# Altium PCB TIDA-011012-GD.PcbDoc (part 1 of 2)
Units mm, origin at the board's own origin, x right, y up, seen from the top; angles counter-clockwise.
Board outline 56 x 53 mm, 4 copper layers (Top Layer, Layer 1, Layer 2, Bottom Layer), stack 1.787 mm thick; 152 components, 63 nets, 416 pads, 728 vias.
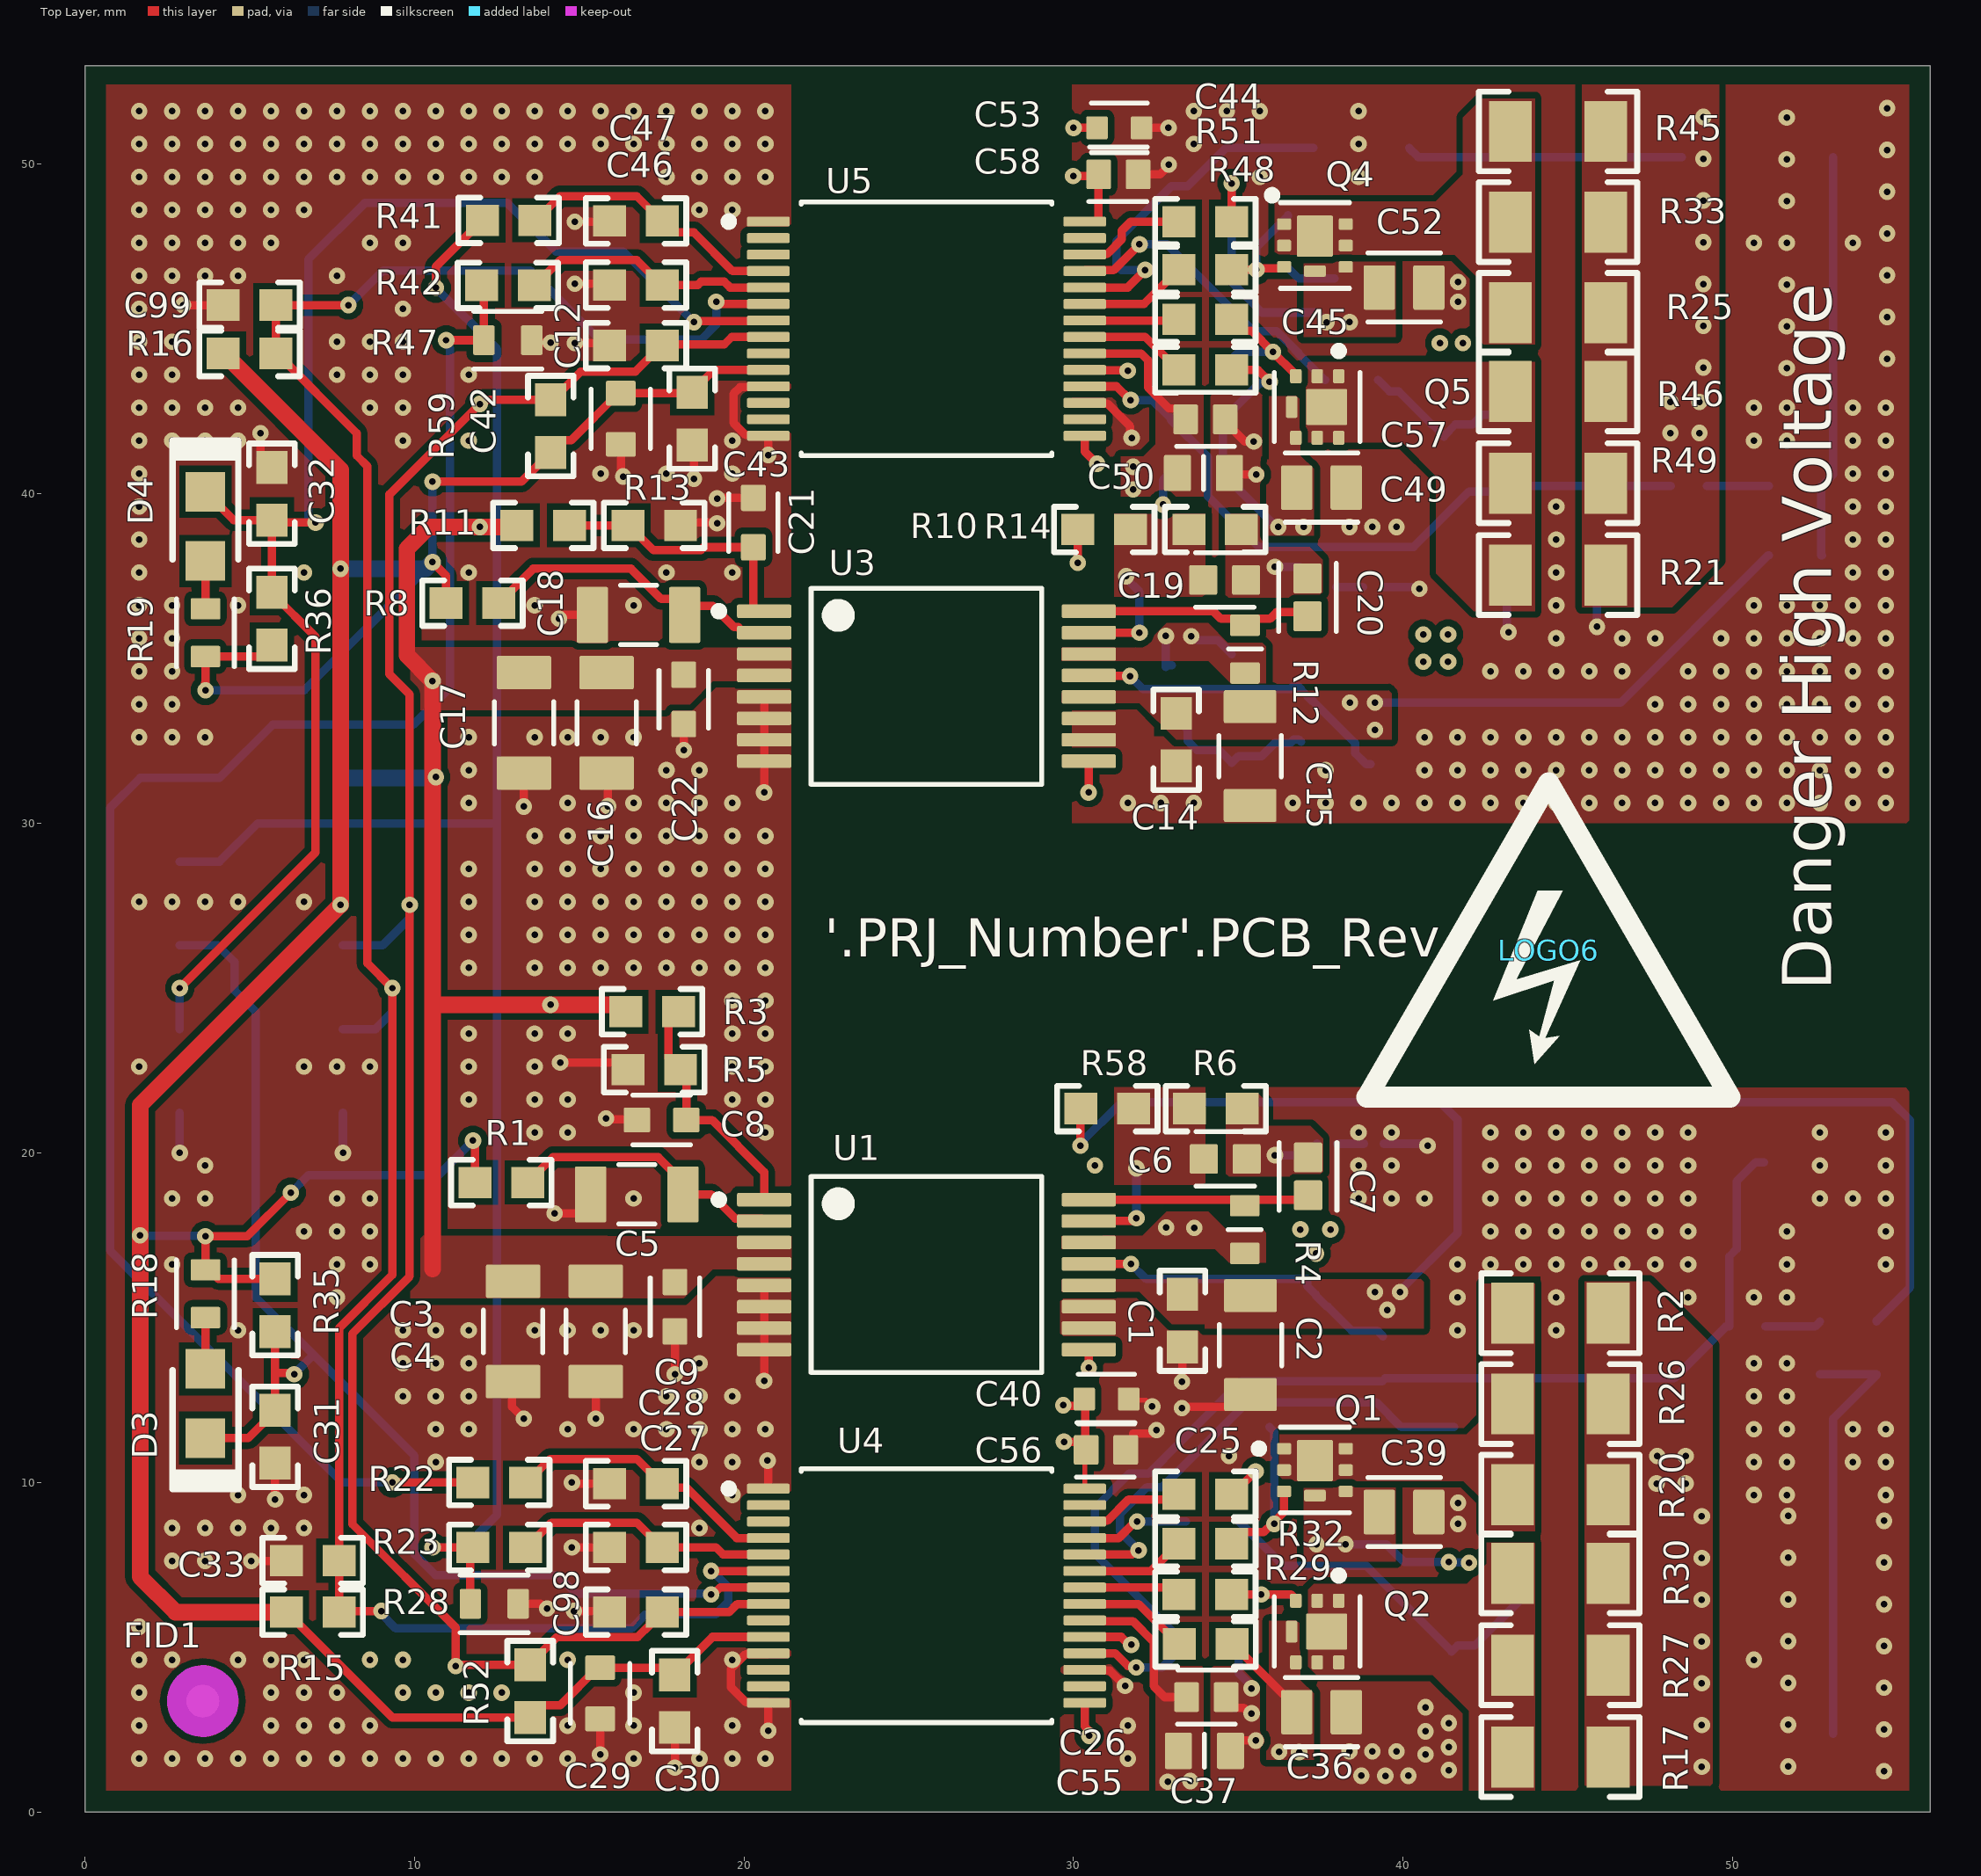
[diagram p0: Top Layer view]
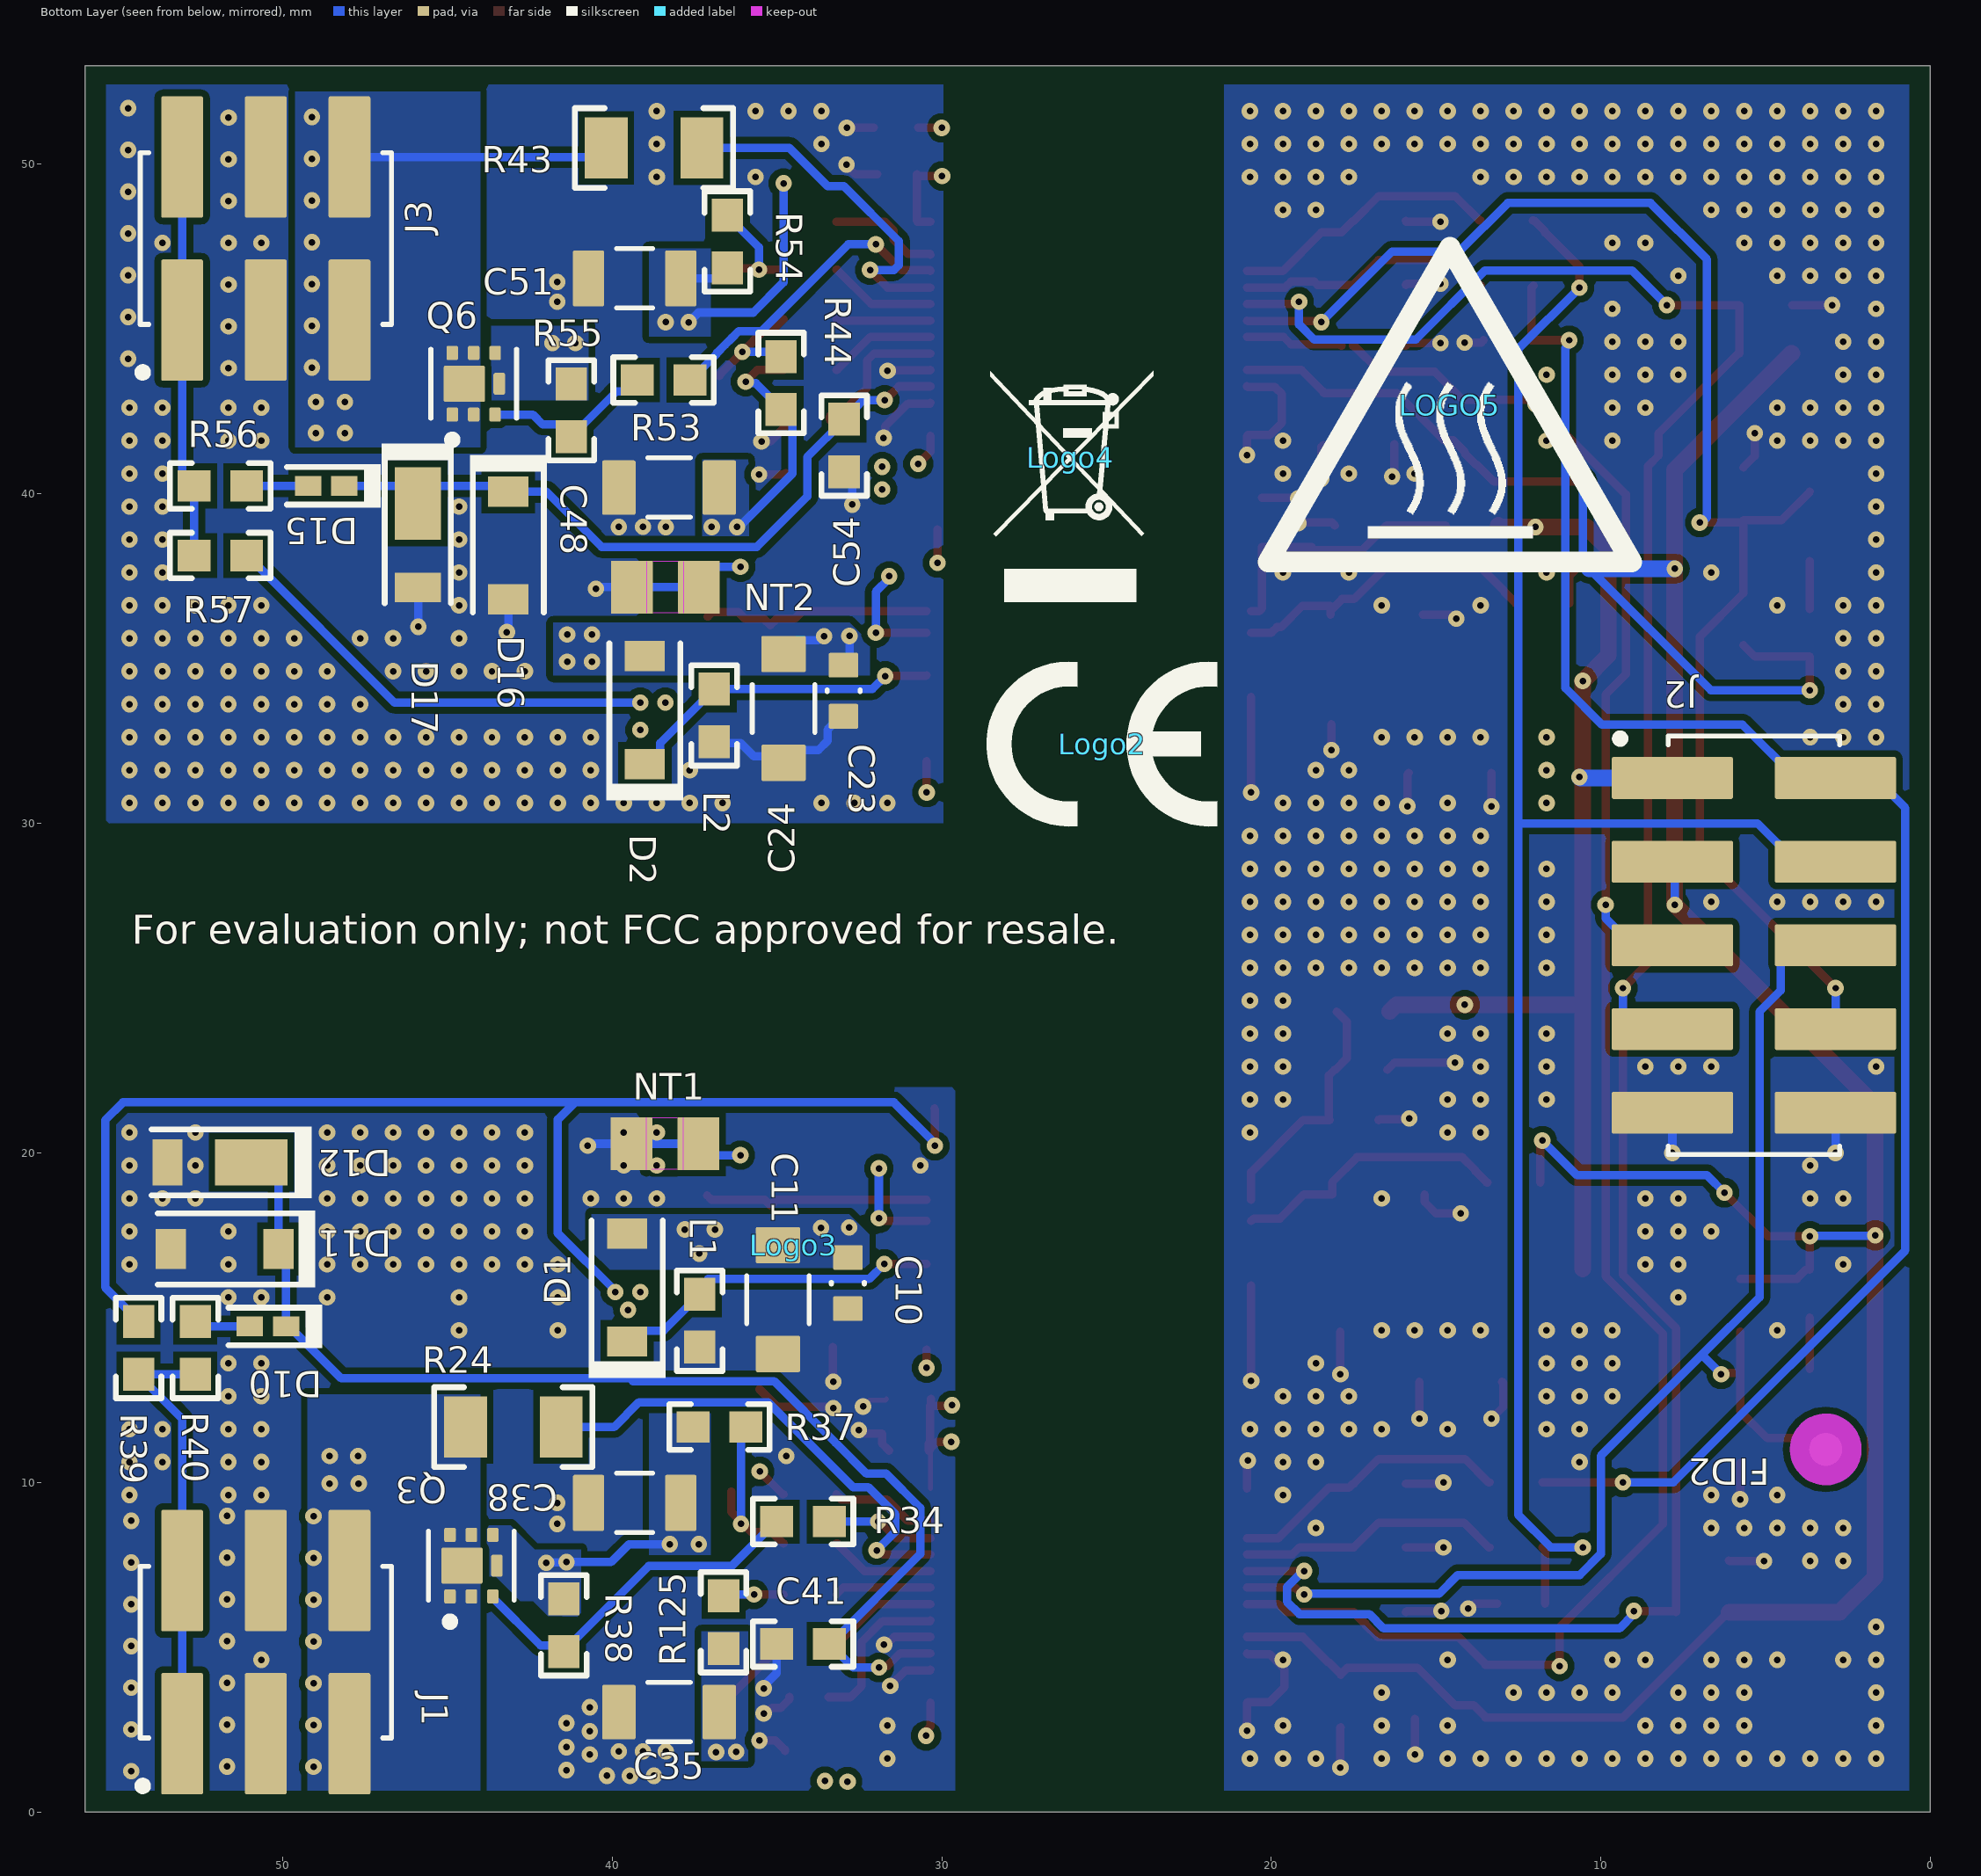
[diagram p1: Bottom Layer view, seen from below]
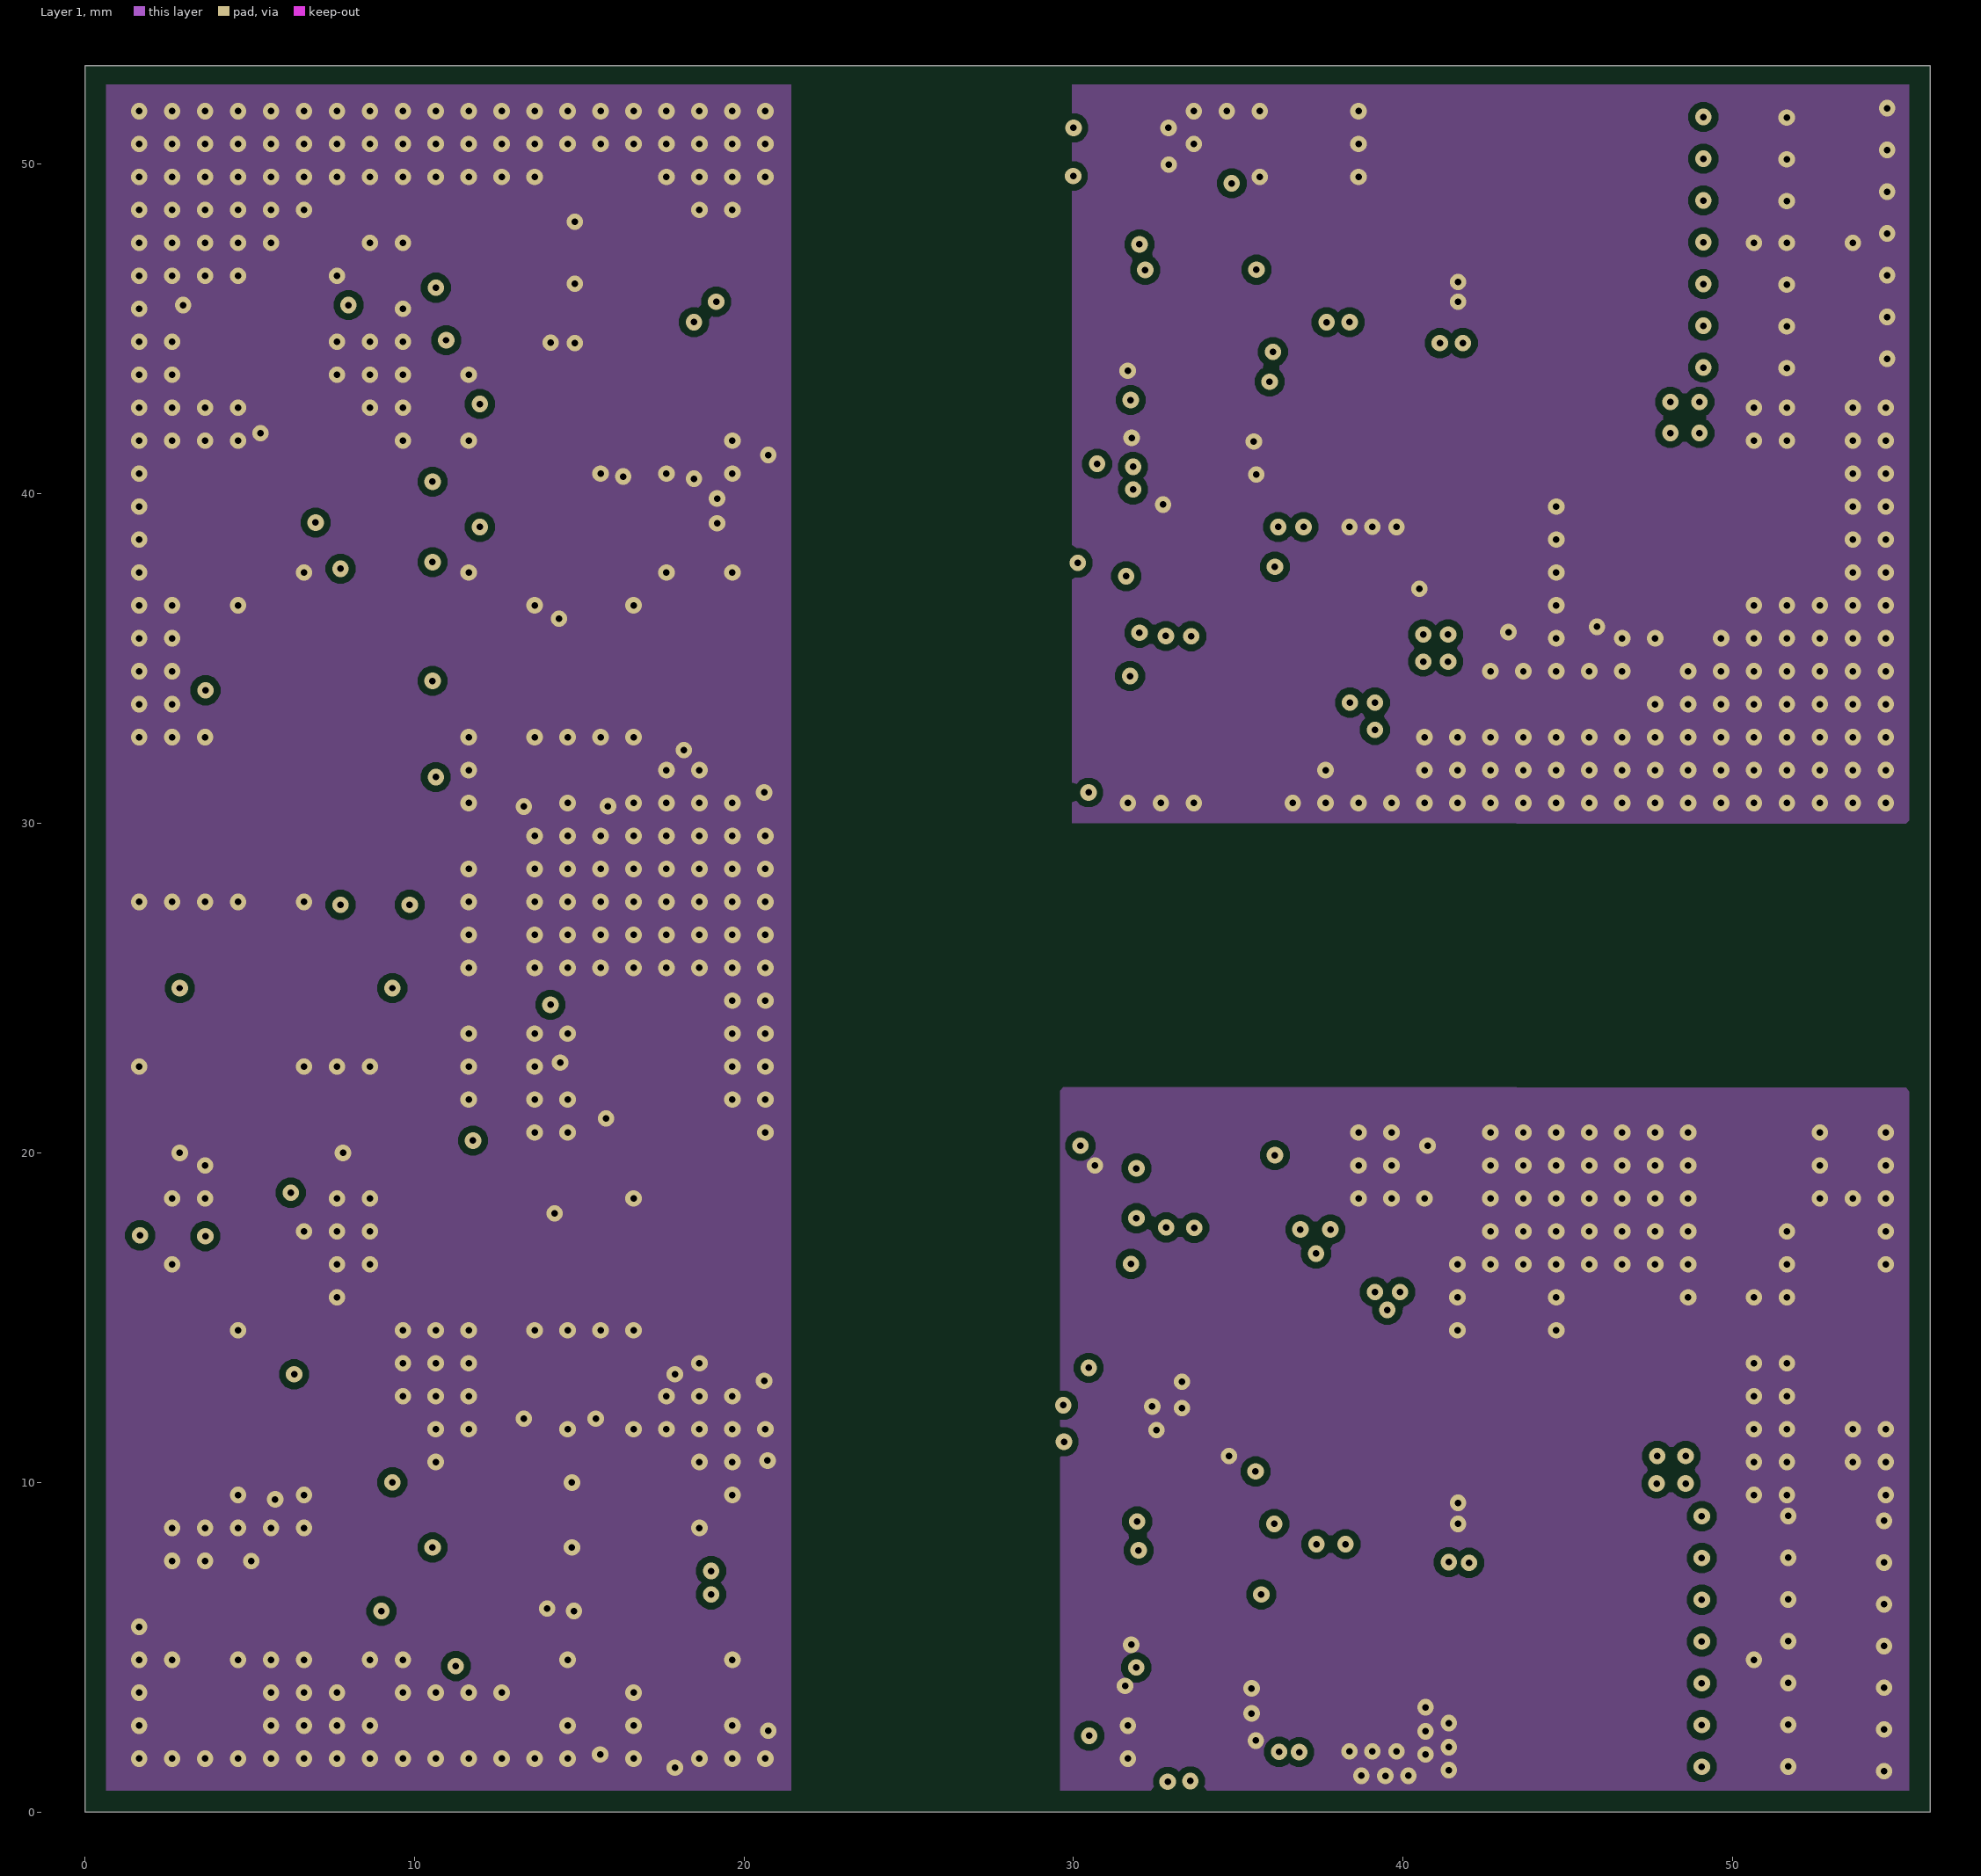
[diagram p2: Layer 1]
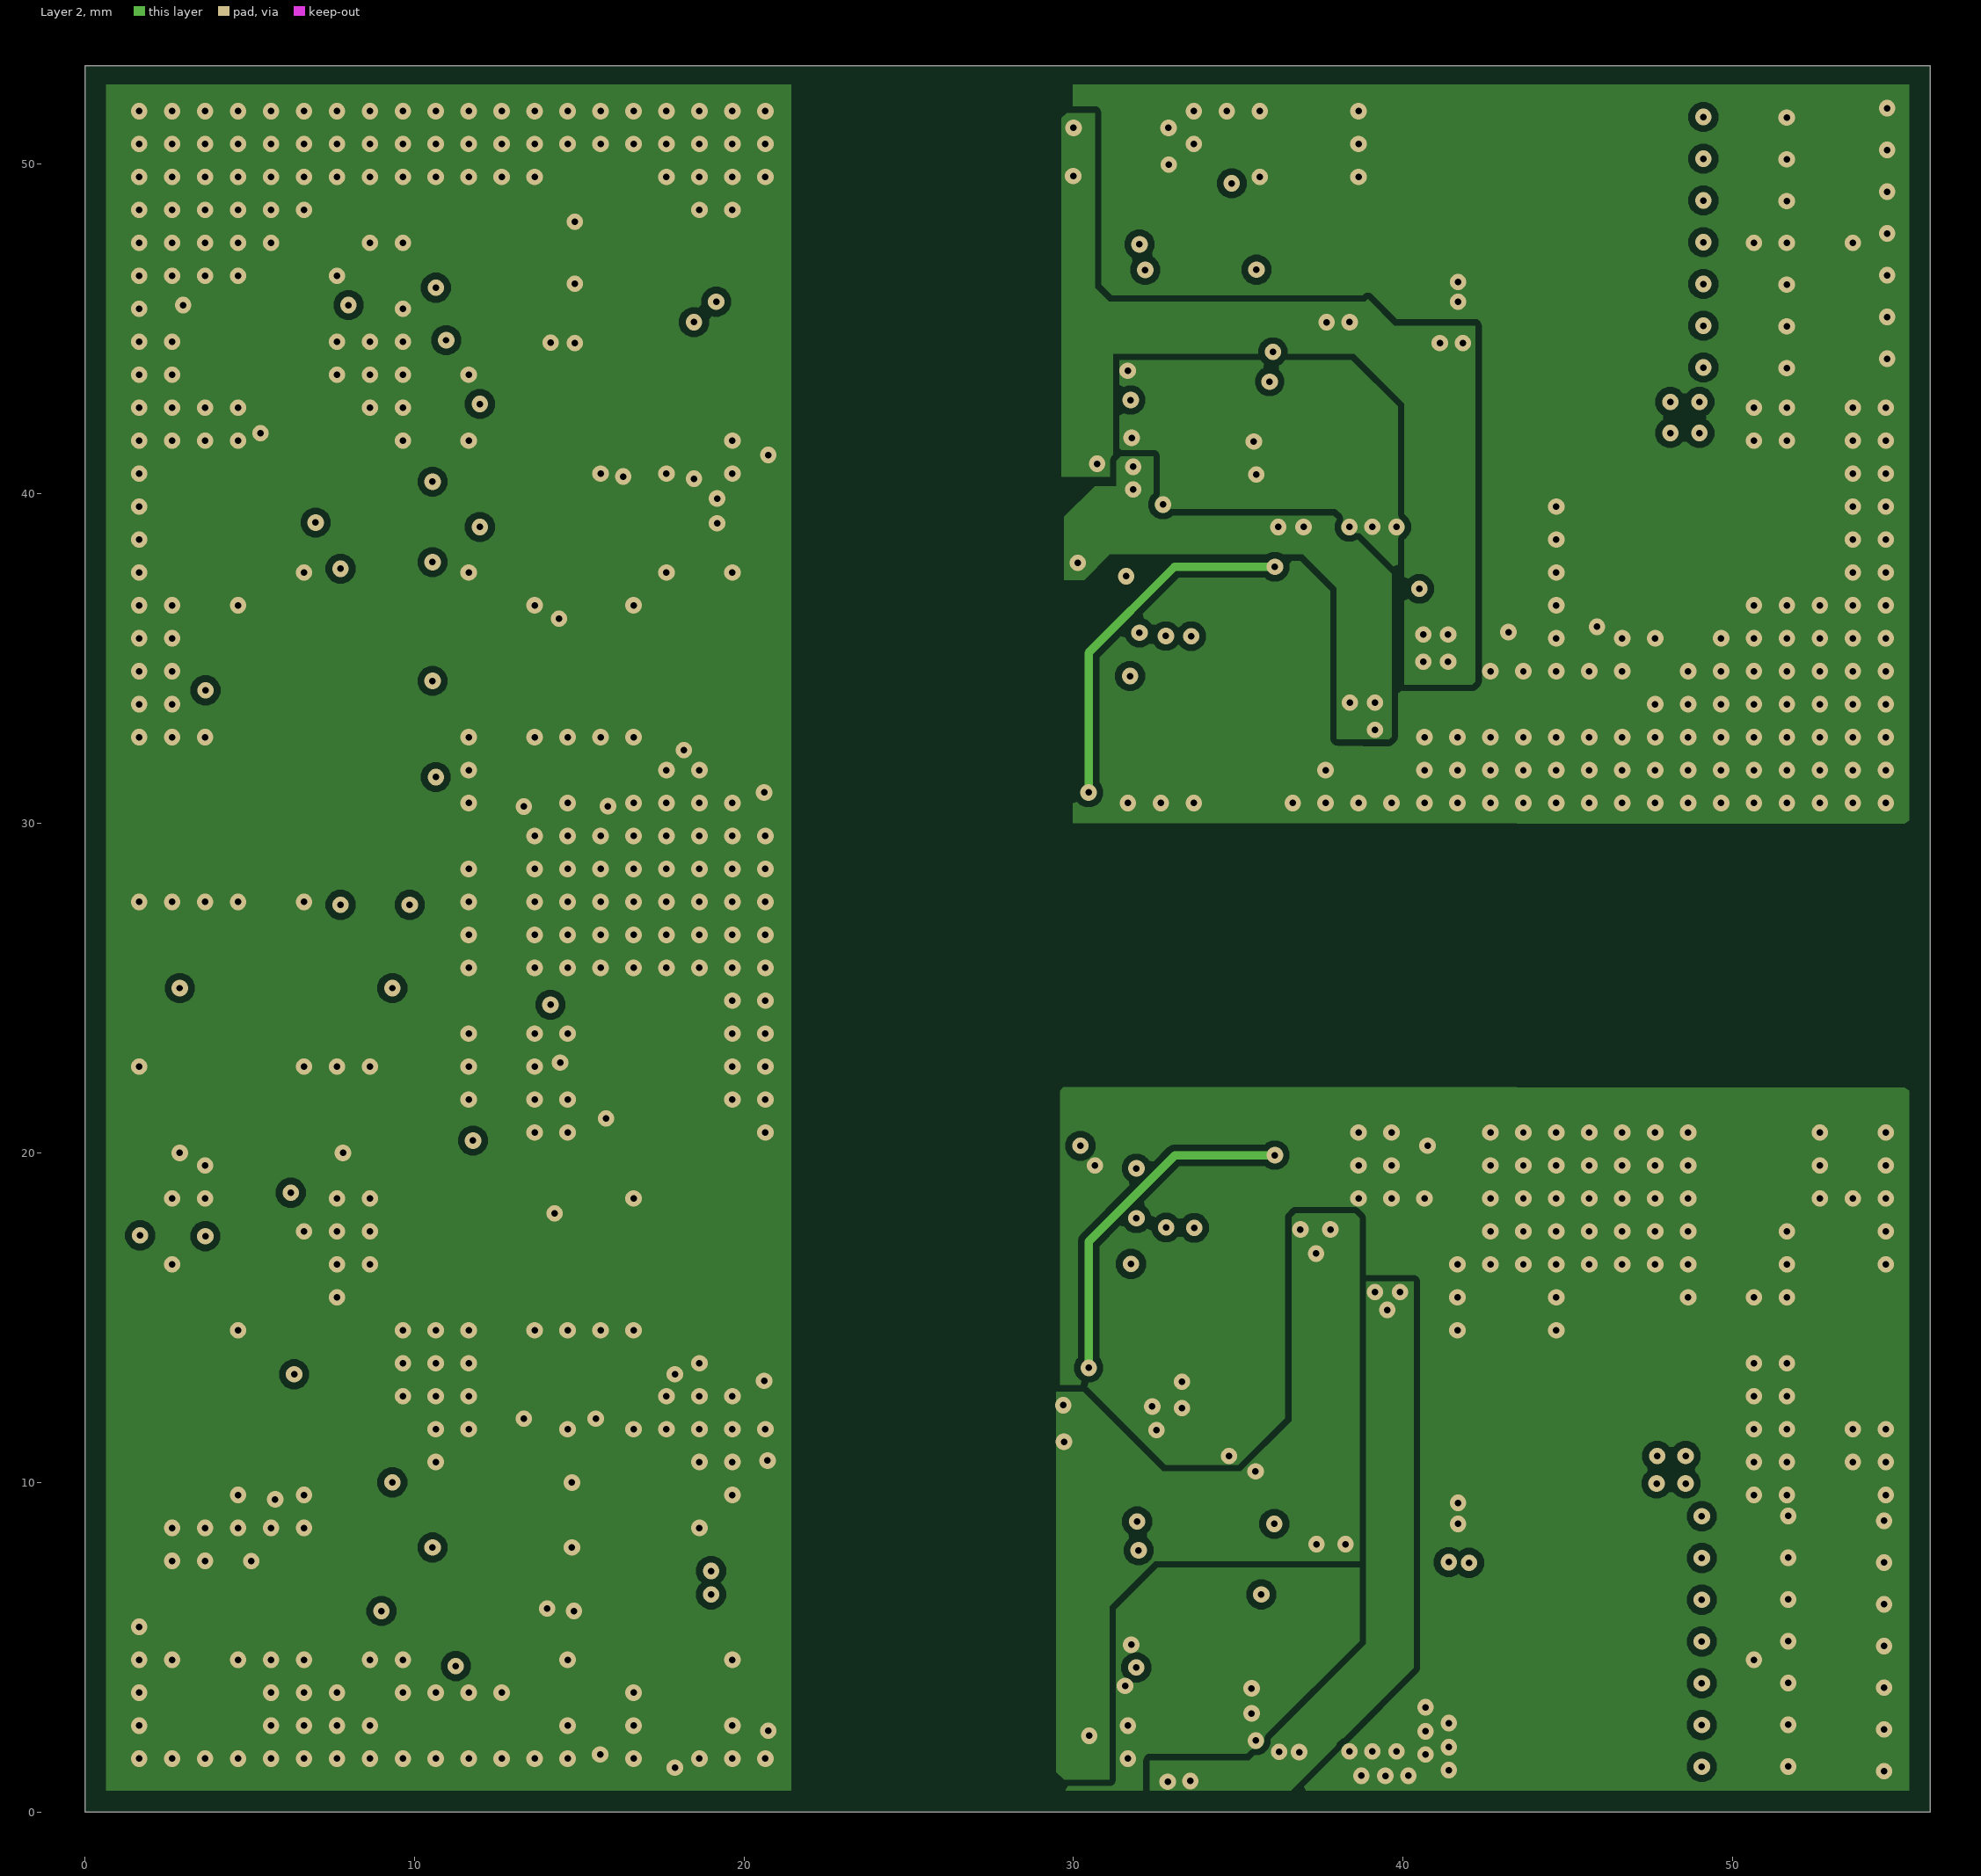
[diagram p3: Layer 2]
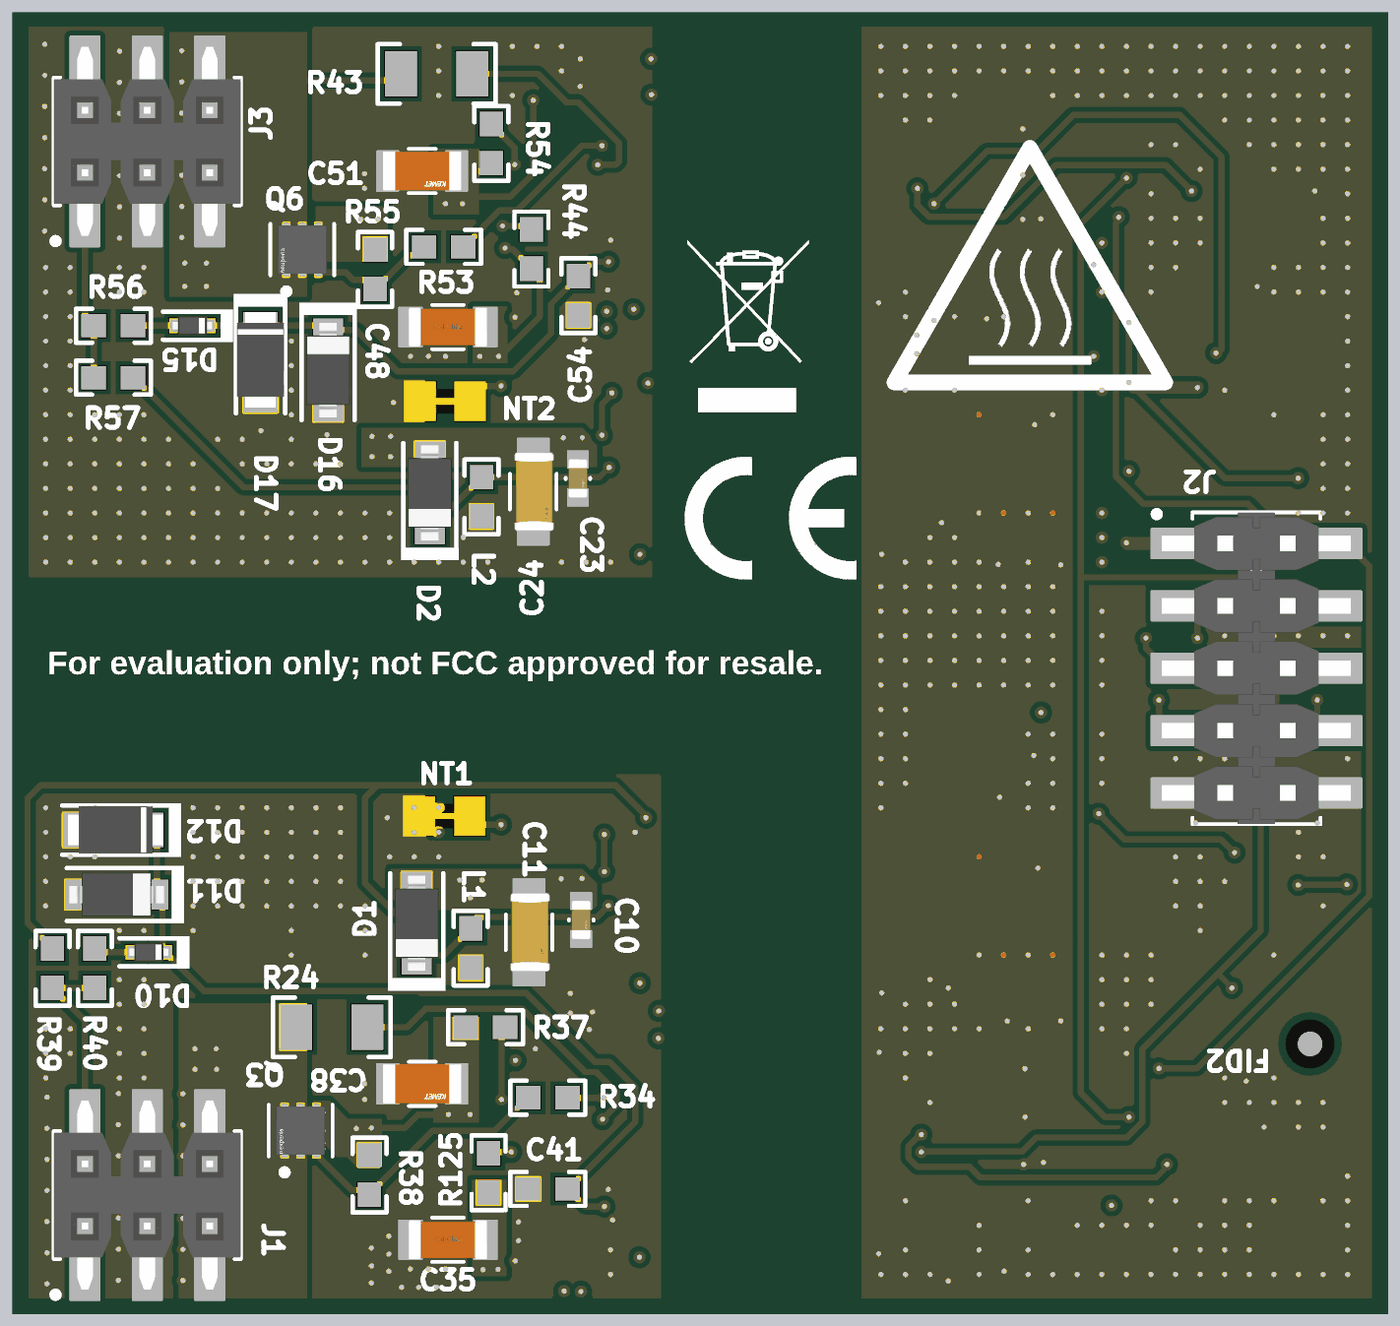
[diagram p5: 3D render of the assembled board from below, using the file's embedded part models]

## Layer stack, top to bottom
Top Solder: solder mask 0.0102, Solder Resist, Dk 3.5
Top Layer: signal copper 0.0356
Dielectric 1: core 0.0711, PP-006, Dk 4.1
Layer 1: signal copper 0.035
Dielectric1: core 1.5037, FR-4 High Tg, Dk 4.8
Layer 2: signal copper 0.035
Dielectric 2: core 0.0711, PP-006, Dk 4.1
Bottom Layer: signal copper 0.0356
Bottom Solder: solder mask 0.0102, Solder Resist, Dk 3.5

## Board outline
0,0 0,53 56,53 56,0

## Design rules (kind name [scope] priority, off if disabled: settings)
AcuteAngle [All] p1: minimum=4.50000000000000E+0001 checktracksonly=FALSE
AssemblyTestPointUsage [All] p1: valid=2
BoardOutlineClearance BoardOutlineClearance_MountingHoles [OnCopper and InComponentClass('Mounting Holes')] p1: gap=1 ignorepadtopadclearanceinfootprint=FALSE
BoardOutlineClearance BoardOutlineClearance_Poly [OnCopper and IsPoly] p2: gap=0.635 ignorepadtopadclearanceinfootprint=FALSE
BoardOutlineClearance [OnCopper and Not InComponentClass('Logo') and not InComponentClass('FiducialMark') and not InRegion(1000,500,4000,800) and not InPoly] p3: gap=0.4 ignorepadtopadclearanceinfootprint=FALSE
Clearance Clearance_HV_BOT [InNetClass('HV_BOT') vs InNetClass('HV_TOP') OR InNetClass('LV')] p1: gap=8 ignorepadtopadclearanceinfootprint=TRUE
Clearance Clearance_HV_TOP [InNetClass('HV_TOP') vs InNetClass('LV') OR InNetClass('HV_BOT')] p2: gap=8 ignorepadtopadclearanceinfootprint=TRUE
Clearance Clearance_Keepouts [((IsTrack Or IsArc) And Not InPoly) And IsFree and IsKeepOut vs ((IsTrack Or IsArc) And Not InPoly) And IsFree and IsKeepOut] p3: gap=0 ignorepadtopadclearanceinfootprint=FALSE
Clearance Clearance_Poly [InPolygon] p4: gap=0.2 ignorepadtopadclearanceinfootprint=TRUE
Clearance Clearance_FiducialMark [IsKeepOut and InComponentClass('FiducialMark') vs IsPad and InComponentClass('FiducialMark')] p5: gap=0 ignorepadtopadclearanceinfootprint=FALSE
Clearance [All] p6: gap=0.15 ignorepadtopadclearanceinfootprint=TRUE
ComponentClearance ComponentClearance_MountingHoles_FiducialMarks [InComponentClass('Mounting Holes') vs InComponentClass('FiducialMark')] p1: gap=1.27 collisioncheckmode=3 verticalgap=0.254 showdistances=FALSE
ComponentClearance ComponentClearance_Shunt [InComponentClass('Header') vs InComponentClass('Shunt')] p2: gap=0 collisioncheckmode=3 verticalgap=0 showdistances=FALSE
ComponentClearance ComponentClearance_Logo [InComponentClass('Logo')] p3: gap=0.762 collisioncheckmode=3 verticalgap=0.254 showdistances=FALSE
ComponentClearance ComponentClearance_ScrewToNut [(HasFootprint('NY PMS 440 0025 PH')) vs (HasFootprint('Keystone_1902C'))] p4: gap=0.127 collisioncheckmode=3 verticalgap=0.254 showdistances=FALSE
ComponentClearance ComponentClearance_MountingHoles [InComponentClass('Mounting Holes')] p5: gap=2.54 collisioncheckmode=3 verticalgap=2540 showdistances=FALSE
ComponentClearance ComponentClearance_SmallPassives [HasFootprint('0201*') or HasFootprint('0402*') or HasFootprint('0508') or HasFootprint('0603*') or HasFootprint('0612') or HasFootprint('0805*') or HasFootprint('0815*') or HasFootprint('0830*') or HasFootprint('1206*') or HasFootprint('1210*') or HasFootprint('1808*') or HasFootprint('1812*') or HasFootprint('1825*') or HasFootprint('2010*') or HasFootprint('2220*') or HasFootprint('2225*') or HasFootprint('2512*') or HasFootprint('2728*') or HasFootprint('3518*') vs HasFootprint('0201*') or HasFootprint('0402*') or HasFootprint('0508') or HasFootprint('0603*') or HasFootprint('0612') or HasFootprint('0805*') or HasFootprint('0815*') or HasFootprint('0830*') or HasFootprint('1206*') or HasFootprint('1210*') or HasFootprint('1808*') or HasFootprint('1812*') or HasFootprint('1825*') or HasFootprint('2010*') or HasFootprint('2220*') or HasFootprint('2225*') or HasFootprint('2512*') or HasFootprint('2728*') or HasFootprint('3518*')] p6: gap=0.38 collisioncheckmode=3 verticalgap=0.254 showdistances=FALSE
ComponentClearance ComponentClearance_THtoSMT [IsThruComponent vs IsSMTComponent] p7: gap=0.762 collisioncheckmode=3 verticalgap=0.762 showdistances=FALSE
ComponentClearance ComponentClearance_THtoTH [IsThruComponent vs IsThruComponent] p8: gap=0.508 collisioncheckmode=3 verticalgap=0.762 showdistances=FALSE
ComponentClearance [All] p9: gap=0.508 collisioncheckmode=3 verticalgap=0.254 showdistances=FALSE
DiffPairsRouting [All] p1: maxlimit=2.54 minlimit=0.254 mostfreqgap=0.254 toplayer_minwidth=0.381 toplayer_maxwidth=0.381 toplayer_prefwidth=0.381 midlayer1_minwidth=0.381 midlayer1_maxwidth=0.381 midlayer1_prefwidth=0.381 midlayer2_minwidth=0.381 midlayer2_maxwidth=0.381 midlayer2_prefwidth=0.381 bottomlayer_minwidth=0.381 bottomlayer_maxwidth=0.381 bottomlayer_prefwidth=0.381 maxuncoupledlength=25.4
FabricationTestPointUsage TestPointUsage [All] p1: valid=2 allowmultiple=FALSE
FabricationTestpoint Testpoint [All] p1: side=3 testpointundercomponent=TRUE minsize=1.016 maxsize=2.54 preferedsize=1.524 minholesize=0 maxholesize=1.016 preferedholesize=0.813 testpointgrid=0.025 allowsidetop=TRUE allowsidebottom=TRUE usegrid=TRUE gridtolerance=0
FanoutControl Fanout_LCC [IsLCC] p1: bgadir=Out bgaviamode=Centered fanoutstyle=Auto fanoutdirection=Alternating viagrid=0.025 // Fanout_LCC (Default Rule)
FanoutControl Fanout_BGA [IsBGA] p2: bgadir=Out bgaviamode=Centered fanoutstyle=Auto fanoutdirection=Alternating viagrid=0.025 // Fanout_BGA (Default Rule)
FanoutControl Fanout_Default [All] p4: bgadir=Out bgaviamode=Centered fanoutstyle=Auto fanoutdirection=Alternating viagrid=0.025 // Fanout_Default (Default Rule)
FanoutControl Fanout_Small [(CompPinCount < 5)] p5: bgadir=Out bgaviamode=Centered fanoutstyle=Auto fanoutdirection=OutThenIn viagrid=0.025 // Fanout_Small (Default Rule)
HoleSize [All] p1: absolutevalues=TRUE maxlimit=6.375 minlimit=0.2 maxpercent=80.000 minpercent=20.000
MinimumAnnularRing MinimumAnnularRing_ThermalPadVias [IsVia and InAnyComponent] p1: minimumring=0.15
MinimumAnnularRing [All] p2: minimumring=0.15
MinimumSolderMaskSliver MinimumSolderMaskSliver_Logo [InComponentClass('Logo') vs InComponentClass('Logo')] p1: minsoldermaskwidth=0.018
MinimumSolderMaskSliver [All] p2: minsoldermaskwidth=0.1
PlaneConnect [All] p1: planeconnectstyle=Relief reliefexpansion=0.254 reliefentries=4 reliefconductorwidth=0.254 reliefairgap=0.254
PolygonConnect [All] p1: thpad.connectstyle=Relief thpad.reliefconductorwidth=0.75 thpad.reliefentries=4 thpad.polygonreliefangle="90 Angle" thpad.airgapwidth=0.25 smdpad.connectstyle=Direct smdpad.reliefconductorwidth=0.254 smdpad.reliefentries=4 smdpad.polygonreliefangle="90 Angle" smdpad.airgapwidth=0.254 via.connectstyle=Direct via.reliefconductorwidth=0.254 via.reliefentries=4 via.polygonreliefangle="90 Angle" via.airgapwidth=0.254
RoutingVias ThermalPadVias [IsVia and InAnyComponent] p1: holewidth=0.2 width=0.5 viastyle="Through Hole" minholewidth=0.2 minwidth=0.5 maxholewidth=0.33 maxwidth=0.6
RoutingVias [All] p2: holewidth=0.406 width=0.864 viastyle="Through Hole" minholewidth=0.2 minwidth=0.61 maxholewidth=1.016 maxwidth=1.651 useviatemplates=TRUE viatemplateguid#1={42D35BA7-5C9A-4F08-859A-22553A785AD8} viatemplatename#1=v50h20m0mx0
SilkToBoardRegionClearance [Not ((IsComment or IsDesignator) And (Hide <> 'False')) and not InRegion(1000,500,4000,800)] p1:
SilkToSilkClearance SilkToSilkClearance_Pb-FreeLogo [(HasFootprint('Pb-Free_Overlay_Medium') OR HasFootprint('Pb-Free_Overlay_Small')) vs (HasFootprint('Pb-Free_Overlay_Medium') OR HasFootprint('Pb-Free_Overlay_Small'))] p1: silktosilkclearance=0
SilkToSilkClearance [All] p2: silktosilkclearance=0
SilkToSolderMaskClearance SilkToComponentPadClearance [(IsPad or IsFill or IsRegion) and InAnycomponent] p1: minsilkscreentomaskgap=0.127 clearancetoexposedcopper=TRUE
SilkToSolderMaskClearance "Silk to Solder Mask Opening" [All] p2: minsilkscreentomaskgap=0.1 clearancetoexposedcopper=FALSE
SolderMaskExpansion [All] p1: expansion=0.05 istentingtop=FALSE
UnRoutedNet [All] p1: checkbadconnections=TRUE
Width [All] p1: maxlimit=2.54 minlimit=0.152 preferedwidth=0.254 checkconnectedcopper=TRUE
14 further rules are at their usual default settings.

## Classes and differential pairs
net class LV: 5V 12V BUF_PWM1 BUF_PWM2 FAULT_FET1 FAULT_FET2 GD_RDY GD_RST/EN GND NetC5_2 NetC8_2 NetC18_2 NetC21_2 NetC27_1 NetC28_1 NetC46_1 NetC47_1 NetD3_1 NetD4_1 NetU5_2 NetU5_3 NetU5_9 NetU5_12 NetU5_13
net class HV_TOP: +18V_TOP -5V_TOP BF_OFF_TOP BF_ON_TOP CLMPE_TOP DS1 G1 KS1 NetC6_1 NetC6_2 NetC7_2 NetC25_2 NetC26_2 NetD1_1 NetD10_2 NetQ1_3 NetQ2_3 NetQ3_3 NetR24_1 NetU4_16 NetU4_27 OC_TOP OUTN_TOP OUTP_TOP
net class HV_BOT: +18V_BOT -5V_BOT BF_OFF_BOT BF_ON_BOT CLMPE_BOT DS2 G2 KS2 NetC19_1 NetC19_2 NetC20_2 NetC44_2 NetC45_2 NetD2_1 NetD15_2 NetQ4_3 NetQ5_3 NetQ6_3 NetR43_1 NetU5_16 NetU5_27 OC_BOT OUTN_BOT OUTP_BOT
component class TIDA-011012-GD-DCDC-Supplies: C1 C2 C3 C4 C5 C6 C7 C8 C9 C10 C11 C14 C15 C16 C17 C18 C19 C20 C21 C22 C23 C24 D1 D2 L1 L2 NT1 NT2 R1 R3 R4 R5 R6 R8 R10 R11 R12 R13 R14 R58 U1 U3
component class TIDA-011012-GD-Hardware: 222 !PCB FID1 FID2 Logo2 Logo3 Logo4 LOGO5 LOGO6 ZZ1 ZZ2 ZZ3 ZZ4
component class TIDA-011012-GD-Gate-Drivers: C12 C25 C26 C27 C28 C29 C30 C31 C32 C33 C35 C36 C37 C38 C39 C40 C41 C42 C43 C44 C45 C46 C47 C48 C49 C50 C51 C52 C53 C54 C55 C56 C57 C58 C98 C99 D3 D4 D10 D11 D12 D15 D16 D17 J1 J2 J3 Q1 Q2 Q3 Q4 Q5 Q6 R2 R15 R16 R17 R18 R19 R20 R21 R22 R23 R24 R25 R26 R27 R28 R29 R30 R32 R33 R34 R35 R36 R37 R38 R39 R40 R41 R42 R43 R44 R45 R46 R47 R48 R49 R51 R52 R53 R54 R55 R56 R57 R59 R125 U4 U5
component class AssemblyNote: ZZ1 ZZ2 ZZ3 ZZ4
component class FiducialMark: FID1 FID2

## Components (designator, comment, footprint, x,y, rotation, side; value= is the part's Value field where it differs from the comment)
C1 "GCM188R71E104KA57D" 0603 33.305,14.903 r270 top value=0.1uF
C2 "KGM31HR71E106KU" FP-KGM31HR71E106KU_1206-MFG 35.368,14.165 r90 top value=10µF
C3 "GMC31X7R106K50NT" FP-GMC31X7R106K50NT_1206-MFG 15.503,14.58 r90 top value=10µF
C4 "GMC31X7R106K50NT" FP-GMC31X7R106K50NT_1206-MFG 12.995,14.58 r90 top value=10µF
C5 "C1206C105J5RECAUTO" FP-C1206C105J5RECAUTO_1206-MFG 16.748,18.74 r0 top value=1µF
C6 "C0603X471F5GACTU" FP-C0603X471F5GACTU_0603-MFG 34.602,19.815 r180 top value=470pF
C7 "VJ0603D220JLAAJ32" FP-VJ0603D220JLAAJ32_0603-IPC_C 37.117,19.287 r270 top value=22pF
C8 "KGM15BR71H104JT" FP-KGM15BR71H104JT_0603-MFG 17.5,20.997 r0 top value=100nF
C9 "KGM15BR71H104JT" FP-KGM15BR71H104JT_0603-MFG 17.904,15.33 r90 top value=100nF
C10 "GRT188C71E225KE13D" FP-GRT188C71E225KE13D_0603-MFG 32.848,16.047 r270 bottom value=2.2µF
C11 "CGA5L2X7R1E225K160AA" FP-CGA5L2X7R1E225K160AA_1206-MFG 34.968,15.547 r270 bottom value=2.2µF
C12 "C0603C221K5RACTU" 0603 16.725,44.503 r180 top value=220pF
C14 "GCM188R71E104KA57D" 0603 33.112,32.537 r270 top value=0.1uF
C15 "KGM31HR71E106KU" FP-KGM31HR71E106KU_1206-MFG 35.356,32.043 r90 top value=10µF
C16 "GMC31X7R106K50NT" FP-GMC31X7R106K50NT_1206-MFG 15.83,33.05 r90 top value=10µF
C17 "GMC31X7R106K50NT" FP-GMC31X7R106K50NT_1206-MFG 13.322,33.05 r90 top value=10µF
C18 "C1206C105J5RECAUTO" FP-C1206C105J5RECAUTO_1206-MFG 16.8,36.326 r0 top value=1µF
C19 "C0603X471F5GACTU" FP-C0603X471F5GACTU_0603-MFG 34.584,37.387 r180 top value=470pF
C20 "VJ0603D220JLAAJ32" FP-VJ0603D220JLAAJ32_0603-IPC_C 37.098,36.859 r270 top value=22pF
C21 "KGM15BR71H104JT" FP-KGM15BR71H104JT_0603-MFG 20.284,39.13 r270 top value=100nF
C22 "KGM15BR71H104JT" FP-KGM15BR71H104JT_0603-MFG 18.171,33.762 r90 top value=100nF
C23 "GRT188C71E225KE13D" FP-GRT188C71E225KE13D_0603-MFG 32.98,34.025 r270 bottom value=2.2µF
C24 "CGA5L2X7R1E225K160AA" FP-CGA5L2X7R1E225K160AA_1206-MFG 34.8,33.487 r270 bottom value=2.2µF
C25 "GRT188R61H225KE13D" 0603 34,9.639 r180 top value=2.2uF
C26 "GRT188R61H225KE13D" 0603 34.006,5.097 r180 top value=2.2uF
C27 "C0603C221K5RACTU" 0603 16.725,8.023 r180 top value=220pF
C28 "C0603C221K5RACTU" 0603 16.725,9.959 r180 top value=220pF
C29 "GRM188R61E475KE15D" FP-GRM188R61E475KE15D_0603-MFG 15.635,3.597 r90 top value=4.7µF
C30 "GCM188R71E104KA57D" 0603 17.9,3.362 r90 top value=0.1uF
C31 "C0603C221K5RACTU" 0603 5.773,11.382 r270 top value=220pF
C32 "C0603C221K5RACTU" 0603 5.675,40.005 r90 top value=220pF
C33 "C0603C221K5RACTU" 0603 6.912,7.626 r180 top value=220pF
C35 "GMC31X7R106K50NT" FP-GMC31X7R106K50NT_1206-MFG 38.273,3.027 r180 bottom value=10µF
C36 "C0805C104K5RAC7800" FP-C0805C104K5RAC7800_0805-MFG 37.523,3.027 r180 top value=100nF
C37 "CL10B105KB9VPJC" FP-CL10B105KB9VPJC_0603-MFG 33.972,1.851 r180 top value=1µF
C38 "C1206C106J4RACAUTO" FP-C1206C106J4RACAUTO_1206-MFG 39.318,9.377 r0 bottom value=10µF
C39 "C0805C104K5RAC7800" FP-C0805C104K5RAC7800_0805-MFG 40.03,9.099 r0 top value=100nF
C40 "GRM188C71C105KA12D" FP-GRM188C71C105KA12D_0603-MFG 30.998,12.528 r0 top value=1µF
C41 "06033C101KAT2A" 0603 34.204,5.097 r0 bottom value=100pF
C42 "GRM188R61E475KE15D" FP-GRM188R61E475KE15D_0603-MFG 16.262,42.281 r90 top value=4.7µF
C43 "GCM188R71E104KA57D" 0603 18.428,42.281 r90 top value=0.1uF
C44 "GRT188R61H225KE13D" 0603 34,48.262 r180 top value=2.2uF
C45 "GRT188R61H225KE13D" 0603 34,43.762 r180 top value=2.2uF
C46 "C0603C221K5RACTU" 0603 16.725,46.34 r180 top value=220pF
C47 "C0603C221K5RACTU" 0603 16.725,48.281 r180 top value=220pF
C48 "GMC31X7R106K50NT" FP-GMC31X7R106K50NT_1206-MFG 38.273,40.19 r180 bottom value=10µF
C49 "C0805C104K5RAC7800" FP-C0805C104K5RAC7800_0805-MFG 37.523,40.19 r180 top value=100nF
C50 "CL10B105KB9VPJC" FP-CL10B105KB9VPJC_0603-MFG 33.942,40.631 r180 top value=1µF
C51 "C1206C106J4RACAUTO" FP-C1206C106J4RACAUTO_1206-MFG 39.318,46.54 r0 bottom value=10µF
C52 "C0805C104K5RAC7800" FP-C0805C104K5RAC7800_0805-MFG 40.03,46.262 r0 top value=100nF
C53 "GRM188C71C105KA12D" FP-GRM188C71C105KA12D_0603-MFG 31.388,51.109 r0 top value=1µF
C54 "06033C101KAT2A" 0603 32.962,41.465 r270 bottom value=100pF
C55 "C0603C104K5RAC3121" FP-C0603C104K5RAC3121_0603-MFG 34.03,3.483 r180 top value=100nF
C56 "C0603C104K5RAC3121" FP-C0603C104K5RAC3121_0603-MFG 30.981,10.985 r0 top value=100nF
C57 "C0603C104K5RAC3121" FP-C0603C104K5RAC3121_0603-MFG 34,42.262 r180 top value=100nF
C58 "C0603C104K5RAC3121" FP-C0603C104K5RAC3121_0603-MFG 31.36,49.699 r0 top value=100nF
C98 "C0603C221K5RACTU" 0603 16.725,6.06 r180 top value=220pF
C99 "C0603C221K5RACTU" 0603 5,45.729 r180 top value=220pF
D1 "RB060M-40TFTR" SOD-123 39.545,15.914 r90 bottom value=40V
D2 "RB060M-40TFTR" SOD-123 39.009,33.437 r90 bottom value=40V
D3 "LH R974-LP-1" LH_R974_Red 3.659,12.395 r270 top value=Red
D4 "LH R974-LP-1" LH_R974_Red 3.655,39.016 r90 top value=Red
D10 "BZT52C2V7T-7" SOD-523 50.446,14.732 r0 bottom value=2.7V
D11 "MMSZ4701-HE3-08" SOD-123 51.759,17.082 r0 bottom value=14V
D12 "DFLZ30-7" PowerDI123 52.22,19.712 r0 bottom value=30V
D15 "BZT52C2V7T-7" SOD-523 48.674,40.246 r0 bottom value=2.7V
D16 "MMSZ4701-HE3-08" SOD-123 43.151,38.434 r270 bottom value=14V
D17 "DFLZ30-7" PowerDI123 45.901,38.434 r270 bottom value=30V
FID1 "Fiducial" Fiducial10-20#1 3.579,3.362 r90 top
FID2 "Fiducial" Fiducial10-20#2 3.175,11 r270 bottom
J1 "TSM-103-04-T-DV" FP-TSM-103-04-T-DV_HDR10-MFG 50.51,4.847 r180 bottom
J2 "TSM-105-04-T-DV" FP-TSM-105-04-T-DV_HDR10-MFG 5.355,26.297 r270 bottom
J3 "TSM-103-04-T-DV" FP-TSM-103-04-T-DV_HDR10-MFG 50.51,47.747 r180 bottom
L1 "AIML-0603-3R3K-T" 0603 37.344,14.903 r90 bottom value=3.3uH
L2 "AIML-0603-3R3K-T" 0603 36.904,33.275 r90 bottom value=3.3uH
Logo2 "CE Mark" CE_Mark_5mm 25.139,32.409 r180 bottom
Logo3 "FCC disclaimer" FCC_disclaimer 34.501,17.197 r270 bottom
Logo4 "WEEE logo" WEEE_Minimum 26.098,41.089 r180 bottom
LOGO5 "CAUTION HOT SURFACE" IEC_HotSurface_Medium 14.583,42.698 r180 bottom
LOGO6 "DANGER HIGH VOLTAGE" IEC_HighVoltage_Medium 44.414,26.147 r0 top
NT1 "Net-Tie" Net-Tie_0805_HV_NoOverlay 38.401,20.278 r0 bottom net-tie
NT2 "Net-Tie" Net-Tie_0805_HV_NoOverlay 38.383,37.168 r0 bottom net-tie
Q1 "BUK6D23-40EX" FP-BUK6D23-40EX_SOT1220-MFG 37.323,10.374 r0 top
Q2 "BUK6D43-40PX" FP-BUK6D43-40PX_SOT1220-MFG 37.394,5.473 r270 top
Q3 "BUK6D23-40EX" FP-BUK6D23-40EX_SOT1220-MFG 44.271,7.472 r90 bottom
Q4 "BUK6D23-40EX" FP-BUK6D23-40EX_SOT1220-MFG 37.323,47.537 r0 top
Q5 "BUK6D43-40PX" FP-BUK6D43-40PX_SOT1220-MFG 37.394,42.636 r270 top
Q6 "BUK6D23-40EX" FP-BUK6D23-40EX_SOT1220-MFG 44.201,43.341 r90 bottom
R1 "ERJ-3EKF1002V" 0603 12.637,19.099 r180 top value=10.0k
R2 "CRM1206-JW-1R0ELF" 1206 44.771,15.132 r0 top value=1.0
R3 "RC0603JR-0715KL" 0603 17.21,24.283 r180 top value=15k
R4 "ERA-3AED513V" FP-ERA-3AED513V_0603-MFG 35.194,17.673 r90 top value=51k
R5 "RT0603DRE0710KL" 0603 17.275,22.526 r0 top value=10.0k
R6 "RT0603DRE072K4L" 0603 34.315,21.345 r180 top value=2.40k
R8 "ERJ-3EKF1002V" 0603 11.762,36.685 r180 top value=10.0k
R10 "RT0603BRD0715KL" 0603 30.93,38.918 r180 top value=15.0k
R11 "RC0603JR-0715KL" 0603 13.912,39.046 r180 top value=15k
R12 "ERA-3AED513V" FP-ERA-3AED513V_0603-MFG 35.202,35.287 r90 top value=51k
R13 "RT0603DRE0710KL" 0603 17.275,39.046 r180 top value=10.0k
R14 "RT0603DRE072K4L" 0603 34.297,38.918 r180 top value=2.40k
R15 "RC0603JR-075K6L" 0603 6.912,6.06 r180 top value=5.6k
R16 "RC0603JR-075K6L" 0603 5,44.262 r180 top value=5.6k
R17 "CRCW12063R30JNEA" 1206 44.771,1.665 r0 top value=3.3
R18 "ERJ-3GEYJ102V" FP-ERJ-3GEYJ102V_0603-MFG 3.659,15.725 r270 top
R19 "ERJ-3GEYJ102V" FP-ERJ-3GEYJ102V_0603-MFG 3.659,35.787 r90 top
R20 "CRM1206-JW-1R0ELF" 1206 44.771,9.625 r0 top value=1.0
R21 "CRCW12063R30JNEA" 1206 44.701,37.534 r0 top value=3.3
R22 "RT0603BRD07120RL" 0603 12.577,9.993 r0 top value=120
R23 "RT0603BRD07120RL" 0603 12.577,8.023 r0 top value=120
R24 "CRCW120632R4FKEA" 1206 43,11.678 r0 bottom value=32.4
R25 "CRM1206-JW-1R0ELF" 1206 44.701,45.494 r0 top value=1.0
R26 "CRM1206-JW-1R0ELF" 1206 44.771,12.378 r0 top value=1.0
R27 "CRCW12063R30JNEA" 1206 44.771,4.453 r0 top value=3.3
R28 "ERJ-3GEYJ102V" FP-ERJ-3GEYJ102V_0603-MFG 12.422,6.314 r0 top
R29 "RT0603BRD07120RL" 0603 34,6.599 r0 top value=120
R30 "CRCW12063R30JNEA" 1206 44.771,7.242 r0 top value=3.3
R32 "RT0603BRD07120RL" 0603 34,8.139 r0 top value=120
R33 "CRM1206-JW-1R0ELF" 1206 44.701,48.247 r0 top value=1.0
R34 "RC0603FR-0710RL" 0603 34.204,8.81 r0 bottom value=10.0
R35 "RC0603JR-075K6L" 0603 5.773,15.38 r90 top value=5.6k
R36 "RC0603JR-075K6L" 0603 5.675,36.21 r270 top value=5.6k
R37 "ERJ-3EKF1002V" 0603 36.744,11.678 r180 bottom value=10.0k
R38 "ERJ-3EKF1002V" 0603 41.467,5.66 r270 bottom value=10.0k
R39 "ERJ-3EKF1002V" 0603 54.368,14.078 r90 bottom value=10.0k
R40 "ERJ-3EKF1001V" 0603 52.648,14.078 r270 bottom value=1.00k
R41 "RT0603BRD07120RL" 0603 12.859,48.303 r0 top value=120
R42 "RT0603BRD07120RL" 0603 12.834,46.329 r0 top value=120
R43 "CRCW120632R4FKEA" 1206 38.731,50.497 r0 bottom value=32.4
R44 "ERJ-3EKF1002V" 0603 34.875,43.365 r270 bottom value=10.0k
R45 "CRM1206-JW-1R0ELF" 1206 44.701,51.001 r0 top value=1.0
R46 "CRCW12063R30JNEA" 1206 44.701,43.111 r0 top value=3.3
R47 "ERJ-3GEYJ102V" FP-ERJ-3GEYJ102V_0603-MFG 12.834,44.663 r0 top
R48 "RT0603BRD07120RL" 0603 34,45.302 r0 top value=120
R49 "CRCW12063R30JNEA" 1206 44.701,40.322 r0 top value=3.3
R51 "RT0603BRD07120RL" 0603 34,46.802 r0 top value=120
R52 "RC0603JR-075K6L" 0603 13.512,3.668 r270 top value=5.6k
R53 "RC0603FR-0710RL" 0603 38.444,43.456 r0 bottom value=10.0
R54 "ERJ-3EKF1002V" 0603 36.503,47.662 r90 bottom value=10.0k
R55 "ERJ-3EKF1002V" 0603 41.24,42.535 r90 bottom value=10.0k
R56 "ERJ-3EKF1002V" 0603 51.892,38.127 r180 bottom value=10.0k
R57 "ERJ-3EKF1001V" 0603 51.892,40.242 r0 bottom value=1.00k
R58 "RT0603BRD0715KL" 0603 31.026,21.345 r180 top value=15.0k
R59 "RC0603JR-075K6L" 0603 14.136,42.06 r270 top value=5.6k
R125 "ERJ-3EKF1002V" 0603 36.619,5.753 r270 bottom value=10.0k
U1 "UCC35131QDHARQ1" DHA0016A-MFG 25.538,16.305 r0 top
U3 "UCC35131QDHARQ1" DHA0016A-MFG 25.538,34.162 r0 top
U4 "PUCC218915AQDFPQ1" DFP0028A-MFG 25.538,6.56 r0 top
U5 "PUCC218915AQDFPQ1" DFP0028A-MFG 25.538,45.012 r0 top
ZZ1 "This Assembly Note is for PCB labels only" AssemblyNoteLabel 4.699,100.025 r0 top
ZZ2 "These assemblies are ESD sensitive, ESD precautions shall be observed." AssemblyNote 4.699,97.259 r0 top
ZZ3 "These assemblies must be clean and free from flux and all contaminants. Use of no clean flux is not acceptable." AssemblyNote 4.699,95.01 r0 top
ZZ4 "These assemblies must comply with workmanship standards IPC-A-610 Class 2, unless otherwise specified." AssemblyNote 4.699,92.761 r0 top

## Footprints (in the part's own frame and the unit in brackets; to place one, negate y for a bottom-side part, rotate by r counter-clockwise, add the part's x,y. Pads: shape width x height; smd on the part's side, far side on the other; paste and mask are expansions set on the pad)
0603 [mm] "0603 from SM-752 data"
  rect 1x0.95 smd: 1(-0.8,0) 2(0.8,0)
  silkscreen extent -1.52,-0.69 1.52,0.69, body extent -0.87,-0.47 0.87,0.47, height 1
1206 [mm] "1206 from SM-752 data"
  rect 1.3x1.85 smd: 1(-1.45,0) 2(1.45,0)
  silkscreen extent -2.4,-1.21 2.4,1.21, body extent -1.7,-0.9 1.7,0.9, height 1.35
AssemblyNote [mm] "Assembly Note"
AssemblyNoteLabel [mm] "Assembly Note for PCB Labels"
CE_Mark_5mm [mm] "Minimum text height for CE Mark"
  silkscreen extent -3.5,-2.5 3.5,2.5
DFP0028A-MFG [mm] "Recommended Land Pattern"
  rrect33% 1.3x0.3 smd paste+0 mask+0: 1(-4.8,3.25) 2(-4.8,2.75) 3(-4.8,2.25) 4(-4.8,1.75) 5(-4.8,1.25) 6(-4.8,0.75) 7(-4.8,0.25) 8(-4.8,-0.25) 9(-4.8,-0.75) 10(-4.8,-1.25) 11(-4.8,-1.75) 12(-4.8,-2.25) 13(-4.8,-2.75) 14(-4.8,-3.25) 15(4.8,-3.25) 16(4.8,-2.75) 17(4.8,-2.25) 18(4.8,-1.75) 19(4.8,-1.25) 20(4.8,-0.75) 21(4.8,-0.25) 22(4.8,0.25) 23(4.8,0.75) 24(4.8,1.25) 25(4.8,1.75) 26(4.8,2.25) 27(4.8,2.75) 28(4.8,3.25)
  silkscreen extent -6.12,-3.85 3.8,3.85, body extent -5.15,-3.8 5.15,3.8, height 2.6
DHA0016A-MFG [mm] "Recommended Land Pattern"
  rrect24% 1.65x0.41 smd paste+0 mask+0: 1(-4.925,2.275) 2(-4.925,1.625) 3(-4.925,0.975) 4(-4.925,0.325) 5(-4.925,-0.325) 6(-4.925,-0.975) 7(-4.925,-1.625) 8(-4.925,-2.275) 9(4.925,-2.275) 10(4.925,-1.625) 11(4.925,-0.975) 12(4.925,-0.325) 13(4.925,0.325) 14(4.925,0.975) 15(4.925,1.625) 16(4.925,2.275)
  silkscreen extent -6.42,-2.98 3.5,2.98, body extent -5.15,-2.93 5.15,2.93, height 2.6
FCC_disclaimer [mm]
Fiducial10-20#1 [mm]
  round 1 smd mask+0.5: 33(0,0)
  Top Layer keep-out circle w1.178: c0,0 r0.5
Fiducial10-20#2 [mm]
  round 1 smd mask+0.5: 1(0,0)
  Top Layer keep-out circle w1.178: c0,0 r0.5
FP-BUK6D23-40EX_SOT1220-MFG [mm]
  rrect29% 0.43x0.35 smd paste-1000 mask+0: 1(-0.935,0.65) 2(-0.935,0) 3(-0.935,-0.65) 4(0.935,-0.65) 5(0.935,0) 6(0.935,0.65)
  rrect9% 1.1x1.25 smd paste-1000 mask+0: 7(0,0.285)
  rrect29% 0.66x0.35 smd paste-1000 mask+0: 8(0,-0.775)
  silkscreen extent -1.82,-1.3 1.05,1.3, body extent -1.25,-1.15 1.25,1.15, height 0.25
FP-BUK6D43-40PX_SOT1220-MFG [mm]
  rrect29% 0.43x0.35 smd paste-1000 mask+0: 1(-0.935,0.65) 2(-0.935,0) 3(-0.935,-0.65) 4(0.935,-0.65) 5(0.935,0) 6(0.935,0.65)
  rrect9% 1.1x1.25 smd paste-1000 mask+0: 7(0,0.285)
  rrect29% 0.66x0.35 smd paste-1000 mask+0: 8(0,-0.775)
  silkscreen extent -1.82,-1.3 1.05,1.3, body extent -1.25,-1.15 1.25,1.15, height 0.25
FP-C0603C104K5RAC3121_0603-MFG [mm]
  rrect13% 0.75x0.9 smd paste+0 mask+0: 1(-0.6,0) 2(0.6,0)
  silkscreen extent -0.89,-0.82 0.87,0.82, body extent -0.8,-0.4 0.8,0.4, height 0.87
FP-C0603X471F5GACTU_0603-MFG [mm]
  rrect12% 0.85x0.9 smd paste+0 mask+0: 1(-0.65,0) 2(0.65,0)
  silkscreen extent -0.88,-0.82 0.88,0.82, body extent -1.2,-0.6 1.2,0.6, height 0.25
FP-C0805C104K5RAC7800_0805-MFG [mm]
  rrect11% 0.95x1.35 smd paste+0 mask+0: 1(-0.75,0) 2(0.75,0)
  silkscreen extent -1.1,-1.05 1.1,1.05, body extent -1,-0.63 1,0.63, height 0.88
FP-C1206C105J5RECAUTO_1206-MFG [mm]
  rrect11% 0.95x1.7 smd paste+0 mask+0: 1(-1.4,0) 2(1.4,0)
  silkscreen extent -0.55,-0.9 0.55,0.9, body extent -1.97,-1 1.97,1, height 0.25
FP-C1206C106J4RACAUTO_1206-MFG [mm]
  rrect11% 0.95x1.7 smd paste+0 mask+0: 1(-1.4,0) 2(1.4,0)
  silkscreen extent -0.55,-0.9 0.55,0.9, body extent -1.6,-0.8 1.6,0.8, height 1.8
FP-CGA5L2X7R1E225K160AA_1206-MFG [mm]
  rrect9% 1.1x1.35 smd paste+0 mask+0: 1(-1.65,0) 2(1.65,0)
  silkscreen extent -0.72,-0.95 0.72,0.95, body extent -1.6,-0.76 1.6,0.84, height 1.9
FP-CL10B105KB9VPJC_0603-MFG [mm]
  rrect12% 0.82x1.1 smd paste+0 mask+0: 1(-0.79,0) 2(0.79,0)
  silkscreen extent 0,-0.5 0,0.5, body extent -0.8,-0.4 0.8,0.4, height 1
FP-ERA-3AED513V_0603-MFG [mm]
  rrect15% 0.65x0.9 smd paste+0 mask+0: 1(-0.725,0) 2(0.725,0)
  silkscreen extent 0,-0.5 0,0.5, body extent -0.8,-0.4 0.8,0.4, height 0.55
FP-ERJ-3GEYJ102V_0603-MFG [mm]
  rrect15% 0.65x0.9 smd paste+0 mask+0: 1(-0.725,0) 2(0.725,0)
  silkscreen extent -1.03,-0.87 1.03,0.87, body extent -1.15,-0.58 1.15,0.58, height 0.25
FP-GMC31X7R106K50NT_1206-MFG [mil]
  rrect10% 40x65 smd paste+0 mask+0: 1(-60,0) 2(60,0)
  silkscreen extent -25,-35 25,35, body extent -84,-39 84,39, height 10
FP-GRM188C71C105KA12D_0603-MFG [mm]
  rrect15% 0.65x0.7 smd paste+0 mask+0: 1(-0.675,0) 2(0.675,0)
  silkscreen extent -0.85,-0.75 0.85,0.75, body extent -0.8,-0.4 0.8,0.4, height 0.9
FP-GRM188R61E475KE15D_0603-MFG [mm]
  rrect13% 0.75x0.9 smd paste+0 mask+0: 1(-0.775,0) 2(0.775,0)
  silkscreen extent -0.9,-0.9 0.9,0.9, body extent -1.25,-0.6 1.25,0.6, height 0.25
FP-GRT188C71E225KE13D_0603-MFG [mm] "Recommended Land Pattern"
  rrect13% 0.75x0.9 smd paste+0 mask+0: 1(-0.775,0) 2(0.775,0)
  silkscreen extent -0.03,-0.5 0.03,0.5, body extent -0.8,-0.4 0.8,0.4, height 1
FP-KGM15BR71H104JT_0603-MFG [mm]
  rrect13% 0.8x0.75 smd paste+0 mask+0: 1(-0.75,0) 2(0.75,0)
  silkscreen extent -0.87,-0.75 0.87,0.75, body extent -1.25,-0.58 1.25,0.58, height 0.25
FP-KGM31HR71E106KU_1206-MFG [mm]
  rrect10% 1x1.6 smd paste+0 mask+0: 1(-1.5,0) 2(1.5,0)
  silkscreen extent -0.63,-0.95 0.63,0.95, body extent -2.1,-1.05 2.1,1.05, height 0.25
FP-TSM-103-04-T-DV_HDR10-MFG [mm] "Recommended Land Pattern"
  rrect8% 1.27x3.68 smd paste+0 mask+0: 1(-2.54,-2.475) 2(-2.54,2.475) 3(0,-2.475) 4(0,2.475) 5(2.54,-2.475) 6(2.54,2.475)
  silkscreen extent -3.86,-4.18 3.81,2.61, body extent -3.81,-3.85 3.81,3.85, height 7.37
FP-TSM-105-04-T-DV_HDR10-MFG [mm] "Recommended Land Pattern"
  rrect8% 1.27x3.68 smd paste+0 mask+0: 1(-5.08,-2.475) 2(-5.08,2.475) 3(-2.54,-2.475) 4(-2.54,2.475) 5(0,-2.475) 6(0,2.475) 7(2.54,-2.475) 8(2.54,2.475) 9(5.08,-2.475) 10(5.08,2.475)
  silkscreen extent -6.4,-4.19 6.35,2.61, body extent -6.35,-3.85 6.35,3.85, height 7.37
FP-VJ0603D220JLAAJ32_0603-IPC_C [mm]
  rrect12% 0.907x0.858 smd paste+0 mask+0: 1(-0.576,0) 2(0.576,0)
  silkscreen extent -1.03,-0.87 1.03,0.87, body extent -1.13,-0.58 1.13,0.58, height 0.25
IEC_HighVoltage_Medium [mm]
  silkscreen extent -5.51,-4.46 5.51,5.09
IEC_HotSurface_Medium [mm]
  silkscreen extent -5.51,-4.76 5.51,4.78
LH_R974_Red [mm] "SMD, 2-Leads, Body 1.2x2mm"
  rect 1.2x1.2 smd: 1(-1.05,0) 2(1.05,0)
  silkscreen extent -1,-1 2.6,1, body extent -1.05,-0.68 1.05,0.68, height 0.9
Net-Tie_0805_HV_NoOverlay [mil] "0805_HV pads tied by 10mil copper trace which can be cut.  An 0805 part can be placed on pads."
  rect 50x63 smd paste-25: 1(-40,0) 2(40,0)
  Top Layer lines w10: -16,0 16,0
  Top Layer keep-out lines w1: -22,30.91 -22,-30.91 ; -14.96,30.91 14.96,30.91 ; -14.96,-30.91 14.96,-30.91 ; 22,30.91 22,-30.91
PowerDI123 [mm] "Diodes Inc recommended land pattern, document number DS30628 Rev. 6-2"
  rect 2.2x1.4 smd: 1(-1.275,0)
  rect 0.9x1.4 smd: 2(1.275,0)
  silkscreen extent -3.1,-1.09 1.76,1.09, body extent -2.37,-0.96 1.53,0.97, height 1
SOD-123 [mm] "On Semi recommended land pattern"
  rect 0.915x1.22 smd: 1(-1.637,0) 2(1.637,0)
  silkscreen extent -2.74,-1.17 2.03,1.17, body extent -1.93,-0.9 1.93,0.9, height 1.35
SOD-523 [mm] "NXP Semiconductor recommended land pattern, nominal STEP model"
  rect 0.8x0.6 smd paste-0.05: 1(-0.55,0) 2(0.55,0)
  silkscreen extent -1.65,-0.66 1.2,0.66, body extent -0.8,-0.4 0.8,0.4, height 0.72
WEEE_Minimum [mm] "WEEElie bin"
  silkscreen extent -2.42,-4.38 2.52,2.65

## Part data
C1 C14 C30 C43: library part CMP-0084679-1, "CAP, CERM, 0.1 µF, 25 V,+/- 10%, X7R, AEC-Q200 Grade 1, 0603", Cap_Case=0603, Manufacturer=MuRata, TempCo=X7R, Tolerance_%=10%, Value2=25V, ValueDisplayed=0.1µF
C2 C15: library part CMP-0044202-1, "10 µF ±10% 25V Ceramic Capacitor X7R 1206 (3216 Metric)", Digikey Part Number=478-KGM31HR71E106KUCT-ND, Manufacturer="KYOCERA AVX", Mouser Part Number=581-KGM31HR71E106KU, Operating Temperature Range="-55°C to +125°C", TempCo=15%, Temperature Characteristic=X7R, Tolerance_%=10%, ValueDisplayed=10uF
C3 C4 C16 C17 C35 C48: library part CMP-0093201-1, "10 µF ±10% 50V Ceramic Capacitor X7R 1206 (3216 Metric)", Manufacturer="Cal-Chip Electronics", Operating Temperature Range="-55°C to +125°C", TempCo=15%, Temperature Characteristic=X7R, Tolerance_%=10%, ValueDisplayed=10uF
C5 C18: library part CMP-0094524-1, "1 µF ±5% 50V Ceramic Capacitor X7R 1206 (3216 Metric)", Digikey Part Number=399-C1206C105J5RECAUTOCT-ND, Manufacturer=KEMET, Mouser Part Number=80-C1206C105J5RECAUT, Operating Temperature Range="-55°C to +125°C", TempCo=15%, Temperature Characteristic=X7R, Tolerance_%=5%, ValueDisplayed=1uF
C6 C19: library part CMP-0097612-1, "Cap Ceramic 470pF 50V C0G 1% SMD 0603 125°C Paper T/R", Digikey Part Number=399-C0603X471F5GAC7867CT-ND, Manufacturer=KEMET, Mouser Part Number=80-C0603X471F5G, Operating Temperature Range="-55°C to +125°C", TempCo=30ppm/°C, Temperature Characteristic=C0G, Tolerance_%=1%, ValueDisplayed=470pF
C7 C20: library part CMP-0039814-1, "22 pF ±5% 50V Ceramic Capacitor C0G, NP0 0603 (1608 Metric)", Digikey Part Number=720-VJ0603D220JLAAJ32CT-ND, Manufacturer=Vishay, Operating Temperature Range="-55°C to +150°C", TempCo=30ppm/°C, Temperature Characteristic=C0G, Tolerance_%=5%, ValueDisplayed=22pF
C8 C9 C21 C22: library part CMP-0120061-1, "0.1 µF ±5% 50V Ceramic Capacitor X7R 0603 (1608 Metric)", Digikey Part Number=478-KGM15BR71H104JTCT-ND, Manufacturer="KYOCERA AVX", Mouser Part Number=581-KGM15BR71H104JT, Operating Temperature Range="-55°C to +125°C", TempCo=15%, Temperature Characteristic=X7R, Tolerance_%=5%, ValueDisplayed=0.1uF
C10 C23: library part CMP-0125378-1, "Multi-Layer Ceramic Capacitor 2.2uF 25V X7S ±10% 0603 Paper T/R", Manufacturer=Murata, Operating Temperature Range="-55°C to +125°C", TempCo=22%, Temperature Characteristic=X7S, Tolerance_%=10%, ValueDisplayed=2.2uF
C11 C24: library part CMP-0090741-1, "Cap Ceramic 2.2uF 25V X7R 10% Pad SMD 1206 +125°C Automotive T/R", Manufacturer=TDK, Operating Temperature Range="-55°C to +125°C", TempCo=15%, Temperature Characteristic=X7R, Tolerance_%=0.1%, ValueDisplayed=2.2uF
C12 C27 C28 C31 C32 C33 C46 C47 C98 C99: library part CMP-0006895-4, "CAP, CERM, 220 pF, 50 V, +/- 10%, X7R, 0603", Cap_Case=0603, Manufacturer=Kemet, Supplier Part Number 1=399-1071-1-ND, TempCo=X7R, Tolerance_%=10%, Value1=Unknown, Value2=50V, ValueDisplayed=220pF
C25 C26 C44 C45: library part CMP-0007502-5, "CAP, CERM, 2.2 uF, 50 V, +/- 10%, X5R, AEC-Q200 Grade 3, 0603", Cap_Case=0603, Manufacturer=MuRata, Supplier Part Number 1=490-12332-1-ND, TempCo=X5R, Tolerance_%=10%, Value1=Unknown, Value2=50V, ValueDisplayed=2.2uF
C29 C42: library part CMP-0091702-1, "4.7µF ±10% 25V Ceramic Capacitor X5R 0603 (1608 Metric)", Digikey Part Number=490-14462-1-ND, Manufacturer=Murata, Mouser Part Number=81-GRM188R61E475KE5D, Operating Temperature Range="-55°C to +85°C", TempCo=15%, Temperature Characteristic=X5R, Tolerance_%=10%, ValueDisplayed=4.7uF
C36 C39 C49 C52: library part CMP-0120154-1, "0.1 µF ±10% 50V Ceramic Capacitor X7R 0805 (2012 Metric)", Digikey Part Number=399-C0805C104K5RAC7800CT-ND, Manufacturer=KEMET, Mouser Part Number=80-C0805C104K5R7800, Operating Temperature Range="-55°C to +125°C", TempCo=15%, Temperature Characteristic=X7R, Tolerance_%=10%, ValueDisplayed=0.1uF
C37 C50: library part CMP-0122257-1, "1 µF ±10% 50V Ceramic Capacitor X7R 0603 (1608 Metric)", Digikey Part Number=1276-CL10B105KB9VPJCCT-ND, Manufacturer=Samsung, Mouser Part Number=187-CL10B105KB9VPJC, Operating Temperature Range="-55°C to +125°C", TempCo=15%, Temperature Characteristic=X7R, Tolerance_%=10%, ValueDisplayed=1uF
C38 C51: library part CMP-0094514-1, "10 µF ±5% 16V Ceramic Capacitor X7R 1206 (3216 Metric)", Digikey Part Number=399-C1206C106J4RACAUTOCT-ND, Manufacturer=KEMET, Mouser Part Number=80-C1206C106J4RAUTO, Operating Temperature Range="-55°C to +125°C", TempCo=15%, Temperature Characteristic=X7R, Tolerance_%=5%, ValueDisplayed=10uF
C40 C53: library part CMP-0122429-1, "1 µF ±10% 16V Ceramic Capacitor X7S 0603 (1608 Metric)", Digikey Part Number=490-GRM188C71C105KA12DTR-ND, Manufacturer=Murata, Mouser Part Number=81-GRM188C71C105KA2D, Operating Temperature Range="-55°C to +125°C", TempCo=22%, Temperature Characteristic=X7S, Tolerance_%=10%, ValueDisplayed=1uF
C41 C54: library part CMP-0006751-4, "CAP, CERM, 100 pF, 25 V, +/- 10%, X7R, 0603", Cap_Case=0603, Manufacturer=AVX, Supplier Part Number 1=55J3899, TempCo=X7R, Tolerance_%=10%, Value1=Unknown, Value2=25V, ValueDisplayed=100pF
C55 C56 C57 C58: library part CMP-0093594-1, "0.1 µF ±10% 50V Ceramic Capacitor X7R 0603 (1608 Metric)", Digikey Part Number=399-C0603C104K5RAC3121TR-ND, Manufacturer=KEMET, Mouser Part Number=80-C603C104K5RAC3121, Operating Temperature Range="-55°C to +125°C", TempCo=15%, Temperature Characteristic=X7R, Tolerance_%=10%, ValueDisplayed=0.1uF
D1 D2: library part CMP-0028628-2, "Diode, Schottky, 40 V, 2 A, SOD-123", Manufacturer=Rohm, Value1=2A, Value2=0.56V
D3 D4: library part CMP-0002983-3, "LED, Red, SMD", Color=red, Manufacturer=OSRAM, Value1=W, Value2=1.8V
D10 D15: library part CMP-0005892-4, "Diode, Zener, 2.7 V, 300 mW, SOD-523", Manufacturer="Diodes Inc.", Power_W=300mW, Value1=0.3W
D11 D16: library part CMP-0077574-3, "Diode, Zener, 14 V, 500 mW, AEC-Q101, SOD-123", Manufacturer=Vishay-Semiconductor, Power_W=500mW, Value1=0.5W
D12 D17: library part CMP-0005417-4, "Diode, Zener, 30 V, 1 W, PowerDI123", Manufacturer="Diodes Inc.", Power_W=1W
FID1 FID2: library part CMP-0077181-1, "Fiducial mark.  There is nothing to buy or mount.", Manufacturer=N/A
J1 J3: library part CMP-0128886-1, "Connector Header Surface Mount 6 position 0.100\" (2.54mm)", Digikey Part Number=SAM10275-ND, Manufacturer=Samtec, Mouser Part Number=200-TSM10304TDV, Operating Temperature Range="-55°C to +105°C"
J2: library part CMP-0128887-1, "Connector Header Surface Mount 10 position 0.100\" (2.54mm)", Digikey Part Number=SAM10285-ND, Manufacturer=Samtec, Mouser Part Number=200-TSM10504TDV, Operating Temperature Range="-55°C to +105°C"
L1 L2: library part CMP-0059575-1, "Inductor, Multilayer, Ferrite, 3.3 uH, 0.015 A, 1.55 ohm, SMD", Manufacturer="Abracon Corporation", Supplier Part Number 1=535-11599-1-ND, Value1="1.55 ohm", Value2=0.015A, ValueDisplayed=3.3uH
Logo2: library part CMP-0074844-1
Logo3: library part CMP-0074847-1, "FCC_disclaimer"
Logo4: library part CMP-0074769-1
LOGO5: library part CMP-0074837-2, "IEC 61010-1 Hot Surface Warning", Manufacturer="Texas Instruments"
LOGO6: library part CMP-0074835-1, "IEC 61010-1 High Voltage Warning"
NT1 NT2: library part CMP-0078142-6, "Single point connection between nets.", Manufacturer=N/A
Q1 Q3 Q4 Q6: library part CMP-0120256-1, "N-Channel 40 V 8A (Ta), 19A (Tc) 2.3W (Ta), 15W (Tc) Surface Mount DFN2020MD-6", Digikey Part Number=1727-8336-1-ND, Drain To Source Breakdown Voltage=40V, Input Capacitace At Vds="582pF @ 20V", Manufacturer=Nexperia, Mouser Part Number=771-BUK6D23-40EX, Operating Temperature Range="-55°C to +175°C", Power_W=2.3W, Pulse Drain Current=76A, Typ Forward Diode Voltage=0.8V
Q2 Q5: library part CMP-0120257-1, "P-Channel 40 V 6A (Ta) 15W (Tc) Surface Mount DFN2020MD-6", Digikey Part Number=1727-BUK6D43-40PXCT-ND, Drain To Source Breakdown Voltage=-40V, Input Capacitace At Vds="1260pF @ -20V", Manufacturer=Nexperia, Mouser Part Number=771-BUK6D43-40PX, Operating Temperature Range="-55°C to +175°C", Power_W=2.3W, Pulse Drain Current=-56A, Typ Forward Diode Voltage=-0.8V
R1 R8 R37 R38 R39 R44 R54 R55 R56 R125: library part CMP-0022684-3, "RES, 10.0 k, 1%, 0.1 W, 0603", Manufacturer=Panasonic, Power_W=100mW, Supplier Part Number 1=P10.0KHCT-ND, TempCo="100 ppm/C", Tolerance_%=1%, Value2=0.1W, Value_Code=10k0, ValueDisplayed=10.0k
R2 R20 R25 R26 R33 R45: library part CMP-0018745-2, "RES, 1.0, 5%, 0.5 W, 1206", Manufacturer=Bourns, Power_W=500mW, Supplier Part Number 1=652-CRM1206JW1R0ELF, TempCo="150 ppm/C", Tolerance_%=5%, Value2=0.5W, Value_Code=1R00, ValueDisplayed=1.0
R3 R11: library part CMP-0025890-5, "RES, 15 k, 5%, 0.1 W, 0603", Manufacturer=Yageo, Power_W=100mW, Supplier Part Number 1=311-15KGRCT-ND, TempCo="100 ppm/C", Tolerance_%=5%, Value2=0.1W, Value_Code=15k0, ValueDisplayed=15k
R4 R12: library part CMP-0031881-1, "51 kOhms ±0.5% 0.1W, 1/10W Chip Resistor 0603 (1608 Metric) Automotive AEC-Q200 Thin Film", Digikey Part Number=P123905CT-ND, Manufacturer=Panasonic, Mouser Part Number=667-ERA-3AED513V, Operating Temperature Range="-55°C to +155°C", Power_W=100mW, TempCo=25ppm/°C, Tolerance_%=0.5%
R5 R13: library part CMP-0024586-3, "RES, 10.0 k, 0.5%, 0.1 W, 0603", Manufacturer="Yageo America", Power_W=100mW, Supplier Part Number 1=603-RT0603DRE0710KL, TempCo="50 ppm/C", Tolerance_%=0.5%, Value2=0.1W, Value_Code=10k0, ValueDisplayed=10.0k
R6 R14: library part CMP-0025064-3, "RES, 2.40 k, 0.5%, 0.1 W, 0603", Manufacturer="Yageo America", Power_W=100mW, TempCo="50 ppm/C", Tolerance_%=0.5%, Value2=0.1W, Value_Code=2k40, ValueDisplayed=2.40k
R10 R58: library part CMP-0023780-3, "RES, 15.0 k, 0.1%, 0.1 W, 0603", Manufacturer="Yageo America", Power_W=100mW, TempCo="25 ppm/C", Tolerance_%=0.1%, Value2=0.1W, Value_Code=15k0, ValueDisplayed=15.0k
R15 R16 R35 R36 R52 R59: library part CMP-0025933-5, "RES, 5.6 k, 5%, 0.1 W, 0603", Manufacturer=Yageo, Power_W=100mW, Supplier Part Number 1=311-5.6KGRCT-ND, TempCo="100 ppm/C", Tolerance_%=5%, Value2=0.1W, Value_Code=5k60, ValueDisplayed=5.6k
R17 R21 R27 R30 R46 R49: library part CMP-0018677-3, "RES, 3.3, 5%, 0.25 W, AEC-Q200 Grade 0, 1206", Manufacturer=Vishay-Dale, Power_W=250mW, Supplier Part Number 1=541-3.3ECT-ND, TempCo="200 ppm/C", Tolerance_%=5%, Value2=0.25W, Value_Code=3R30, ValueDisplayed=3.3
R18 R19 R28 R47: library part CMP-0089144-1, "1 kOhms ±5% 0.1W, 1/10W Chip Resistor 0603 (1608 Metric) Automotive AEC-Q200 Thick Film", Digikey Part Number=P1.0KGCT-ND, Manufacturer=Panasonic, Mouser Part Number=667-ERJ-3GEYJ102V, Operating Temperature Range="-55°C to +155°C", Power_W=100mW, TempCo=200ppm/°C, Tolerance_%=5%, Voltage=75V
R22 R23 R29 R32 R41 R42 R48 R51: library part CMP-0023691-3, "RES, 120, 0.1%, 0.1 W, 0603", Manufacturer="Yageo America", Power_W=100mW, TempCo="25 ppm/C", Tolerance_%=0.1%, Value2=0.1W, Value_Code=120R, ValueDisplayed=120
R24 R43: library part CMP-0016910-3, "RES, 32.4, 1%, 0.25 W, AEC-Q200 Grade 0, 1206", Manufacturer=Vishay-Dale, Power_W=250mW, Supplier Part Number 1=541-32.4FCT-ND, TempCo="100 ppm/C", Tolerance_%=1%, Value2=0.25W, Value_Code=32R4, ValueDisplayed=32.4
R34 R53: library part CMP-0022751-4, "RES, 10.0, 1%, 0.1 W, 0603", Manufacturer=Yageo, Power_W=100mW, Supplier Part Number 1=311-10.0HRCT-ND, TempCo="100 ppm/C", Tolerance_%=1%, Value2=0.1W, Value_Code=10R0, ValueDisplayed=10.0
R40 R57: library part CMP-0022680-4, "RES, 1.00 k, 1%, 0.1 W, 0603", Manufacturer=Panasonic, Power_W=100mW, Supplier Part Number 1=P1.00KHCT-ND, TempCo="100 ppm/C", Tolerance_%=1%, Value2=0.1W, Value_Code=1k00, ValueDisplayed=1.00k
U1 U3: library part CMP-0126653-2, "Automotive 2.0W, 12V VIN, High-Density, > 5kVRMS, Isolated DC/DC Module", Manufacturer="Texas Instruments", Max Supply Voltage=20V, Min Supply Voltage=5.5V, Operating Temperature Range="-40°C to +150°C", Output Voltage=-2-8/12-18V
U4 U5: library part CMP-0128293-1, "Single Channel Isolated Pre-Driver for SiC/IGBT with Active Protection", Manufacturer="Texas Instruments", Max Supply Voltage=28V, Min Supply Voltage=3V, Operating Temperature Range="-40°C to +125°C"
ZZ1: library part CMP-0003616-3
ZZ2: library part CMP-0077236-1
ZZ3: library part CMP-0077237-1
ZZ4: library part CMP-0077238-1

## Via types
v1: diameter 0.5, hole 0.2, Top Layer to Bottom Layer, tented both sides, 728 vias

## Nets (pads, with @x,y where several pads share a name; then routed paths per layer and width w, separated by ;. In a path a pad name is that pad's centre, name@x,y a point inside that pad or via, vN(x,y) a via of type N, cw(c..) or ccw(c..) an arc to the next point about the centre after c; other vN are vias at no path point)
5V: C29.2 C30.2 C42.2 C43.2 J2.3 R1.2 R8.2 R15.2 R16.2 R18.1 R19.1 R35.2 R36.2 R52.2 R59.2 U4.10 U5.10 | length 110
  Top Layer w0.254: R18.1@3.659,16.45 3.659,17.421 3.655,17.425 v1(3.655,17.471) 4.929,17.471 v1(6.248,18.79) ; v1(3.659,34.037) 3.646,34.049 3.646,34.26 3.659,34.272 R19.1@3.659,35.062 5.327,35.062 R36.2@5.675,35.41 ; R18.1@3.784,16.45 4.054,16.18 R35.2@5.773,16.18 ; R15.2@6.112,6.06 6.137,6.06 9.328,2.868 R52.2@13.512,2.868 13.512,2.893 13.86,3.241 14.43,3.241 15.56,4.372 C29.2@15.635,4.372 17.69,4.372 C30.2@17.9,4.162 17.9,4.187 18.248,4.535 18.273,4.535 19.048,5.31 U4.10@20.738,5.31 ; v1(10.549,37.929) 10.962,37.516 R8.2@10.962,36.685 ; v1(10.549,40.37) 13.246,40.37 13.763,40.887 13.788,40.887 14.136,41.235 R59.2@14.136,41.26 ; v1(11.777,20.374) 11.837,20.314 R1.2@11.837,19.099 ; R59.2@14.136,41.285 14.484,41.633 14.765,41.633 16.187,43.056 C42.2@16.262,43.056 18.403,43.056 C43.2@18.428,43.081 ; C43.2@18.428,43.106 19.084,43.762 U5.10@20.738,43.762
  Top Layer w0.508: R16.2@4.2,44.262 4.225,44.262 7.758,40.729 v1(7.758,37.728) v1(7.758,27.528) 1.675,21.444 v1(1.675,17.496) 1.675,7.135 2.75,6.06 R15.2@6.112,6.06
  Bottom Layer w0.254: v1(1.675,17.496) 1.687,17.484 3.643,17.484 v1(3.655,17.471) ; v1@3.652,34.044 v1(3.659,34.037) 6.656,34.037 10.347,37.728 ; v1(6.248,18.79) 6.778,19.32 10.723,19.32 v1(11.777,20.374) ; v1(7.758,27.528) 7.758,28.765 J2.3@7.83,28.837 ; v1(10.549,37.929) v1(10.549,40.37)
  Bottom Layer w0.5: v1@10.545,37.925 v1(10.549,37.929)
  Bottom Layer w0.508: v1(7.758,37.728) 10.347,37.728 v1@10.545,37.925
12V: C3.2 C4.2 C9.2 C16.2 C17.2 C22.2 J2.1 R3.2 R11.2 U1.3 U1.4 U3.3 U3.4 | length 34.5
  Top Layer w0.5: 10.549,16.478 v1(10.549,34.322) 9.77,35.101 9.77,38.333 10.433,38.997 v1(11.984,38.997) 13.063,38.997 R11.2@13.112,39.046 ; 10.649,24.496 v1(14.127,24.496) 16.198,24.496 R3.2@16.41,24.283
  Bottom Layer w0.508: J2.1@7.83,31.377 10.619,31.377 v1(10.648,31.406)
+18V_BOT: C14.1 C15.2 C45.1 C48.2 C49.2 C50.2 C57.2 Q5.4 Q5.8 R10.2 R44.2 R56.2 U3.12 U5.20 | length 26.6
  Top Layer w0.254: v1(30.13,37.906) R10.2@30.13,38.918 ; U5.20@30.338,44.262 32.05,44.262 32.263,44.05 32.263,43.225 32.902,42.585 33.152,42.585 33.4,42.337 C57.2@33.4,42.262 C57.2@33.276,42.138 ; C45.1@34.8,43.762 35.591,43.762 v1(35.948,43.406)
  Bottom Layer w0.254: v1(35.948,43.406) 35.901,43.359 35.644,43.359 34.875,42.59 R44.2@34.875,42.565 34.534,42.224 34.534,40.61 v1@36.208,38.935 ; v1(39.143,33.665) 46.605,33.665 51.067,38.127 R56.2@51.092,38.127
  other v1: 39.143,32.839 38.389,33.665 36.208,38.997 36.979,38.997 31.805,40.131 31.805,40.822
+18V_TOP: C1.1 C2.2 C26.1 C35.2 C36.2 C37.2 C55.2 Q2.4 Q2.8 R39.2 R58.2 R125.2 U1.12 U4.20 | length 48.1
  Top Layer w0.254: v1(30.209,20.214) 30.209,21.328 R58.2@30.226,21.345 ; U4.20@30.338,5.81 30.361,5.787 31.798,5.787 32.429,5.156 32.429,3.817 32.764,3.483 C55.2@33.43,3.483 ; C26.1@34.806,5.097 34.831,5.097 36.354,3.575 36.425,3.575 36.773,3.227 C36.2@36.773,3.027
  Bottom Layer w0.254: v1(30.209,20.214) 30.209,20.29 31.451,21.532 41.13,21.532 ; v1(39.906,15.778) 39.906,15.816 41.648,17.558 41.648,21.014 41.13,21.532 ; R39.2@54.368,14.878 54.368,14.903 55.384,15.919 55.384,20.992 54.843,21.532 41.13,21.532
  other v1: 32.857,0.917 33.541,0.937 36.237,1.821 36.847,1.812 39.517,15.232 39.143,15.778
-5V_BOT: C23.1 C24.1 C44.1 C51.1 C52.1 C53.1 C58.1 D2.2 Q4.4 Q4.8 Q6.4 Q6.8 R12.1 R54.1 R55.2 U3.14 U5.15 U5.28 | length 16
  Top Layer w0.254: v1(29.989,49.648) 30.709,49.648 C58.1@30.76,49.699 30.76,48.285 30.737,48.262 U5.28@30.338,48.262 ; v1(30,51.109) C53.1@30.713,51.109 ; U5.15@30.338,41.762 30.338,41.287 v1(30.713,40.912) ; C44.1@34.8,48.262 v1(34.8,49.422)
  Bottom Layer w0.254: v1(32.8,35.687) 32.8,34.752 32.848,34.8 C23.1@32.98,34.8 ; v1(33.572,35.681) 33.638,35.681 33.759,35.56 34.377,35.56 C24.1@34.8,35.137 ; v1(34.8,49.422) 34.8,46.421 35.717,45.504 37.382,45.504 v1(37.679,45.207) ; R54.1@36.503,46.862 36.825,46.54 C51.1@37.918,46.54
  other v1: 40.61,34.908 41.364,34.908 40.61,35.734 41.364,35.734 41.114,44.574 41.811,44.577 38.376,45.21
-5V_TOP: C10.1 C11.1 C25.1 C38.1 C39.1 C40.1 C56.1 D1.2 Q1.4 Q1.8 Q3.4 Q3.8 R4.1 R37.1 R38.1 U1.14 U4.15 U4.28 | length 10.5
  Top Layer w0.152: U4.28@30.338,9.81 30.338,10.904 C56.1@30.398,10.964
  Top Layer w0.254: v1(29.687,12.343) 29.708,12.322 C40.1@30.276,12.322 ; v1(29.708,11.233) 30.15,11.233 30.28,11.103 30.398,10.985 C56.1@30.398,10.964 ; C40.1@30.323,12.528 30.323,12.359 30.361,12.322 30.361,11.183 30.361,11.002 C56.1@30.398,10.964 ; U4.15@30.338,3.31 30.338,2.596 30.474,2.46 v1(30.474,2.311) ; C56.1@30.349,11.233 30.398,11.183 30.398,11.103 C56.1@30.398,10.964 ; C25.1@34.8,9.639 34.825,9.639 35.516,10.33 v1(35.524,10.33)
  Bottom Layer w0.254: v1(38.25,8.124) 39.489,8.124 40.033,7.579 v1(41.387,7.579) 41.399,7.567 41.988,7.567 v1(42,7.556)
  other v1: 37.371,8.124 37.357,16.944 36.882,17.673 37.795,17.673 33.66,17.724 32.808,17.734
BF_OFF_BOT: Q4.1 Q4.2 Q4.5 Q4.6 Q4.7 R25.1 R33.1 R45.1
BF_OFF_TOP: Q1.1 Q1.2 Q1.5 Q1.6 Q1.7 R2.1 R20.1 R26.1
BF_ON_BOT: Q5.1 Q5.2 Q5.5 Q5.6 Q5.7 R21.1 R46.1 R49.1
BF_ON_TOP: Q2.1 Q2.2 Q2.5 Q2.6 Q2.7 R17.1 R27.1 R30.1
BUF_PWM1: J2.2 R22.1 R42.1 R47.1 | length 52.6
  Top Layer w0.254: v1(9.328,10) 11.769,10 R22.1@11.777,9.993 ; v1(10.962,44.663) R47.1@12.109,44.663 12.109,46.254 R42.1@12.034,46.329
  Bottom Layer w0.254: v1(9.328,10) 7.799,10 0.763,17.036 0.763,30.465 1.675,31.377 J2.2@2.88,31.377 4.085,31.377 5.703,32.996 9.967,32.996 11.076,34.104 11.076,44.427 11,44.503 11,44.625 v1(10.962,44.663)
BUF_PWM2: J2.4 R23.1 R28.1 R41.1 | length 56.1
  Top Layer w0.254: v1(10.549,8.023) R23.1@11.777,8.023 11.697,7.944 R28.1@11.697,6.314 ; v1(10.649,46.254) 10.649,46.893 11.686,47.93 11.686,47.955 12.034,48.303 R41.1@12.059,48.303
  Bottom Layer w0.254: J2.4@2.88,28.837 4.085,28.837 5.248,30 12.503,30 12.511,30.008 ; v1(10.549,8.023) 11.516,8.023 12.511,9.019 12.511,44.392 v1(10.649,46.254)
CLMPE_BOT: R53.1 U5.25 | length 9.4
  Top Layer w0.254: U5.25@30.338,46.762 30.361,46.785 31.213,46.785 v1(32,47.572)
  Bottom Layer w0.254: v1(32,47.572) 32.834,47.572 35.465,44.942 36.158,44.942 36.367,44.733 36.575,44.525 36.819,44.281 36.819,44.256 37.619,43.456 R53.1@37.644,43.456
CLMPE_TOP: R34.1 U4.25 | length 3.3
  Top Layer w0.254: U4.25@30.338,8.31 31.37,8.31 31.87,8.81 v1(31.93,8.81)
  Bottom Layer w0.254: v1(31.93,8.81) R34.1@33.404,8.81
DS1: J1.1 J1.2 R39.1 R40.2 | length 13.2
  Bottom Layer w0.254: R40.2@52.648,13.278 R39.1@54.368,13.278 54.368,13.253 53.05,11.935 J1.2@53.05,7.322 J1.1@53.05,2.372
DS2: J3.1 J3.2 R56.1 R57.2 | length 12.3
  Bottom Layer w0.254: R57.2@52.696,40.246 R57.2@52.692,40.242 ; R56.1@52.717,38.127 R56.1@52.692,38.127 R57.2@52.692,40.242 ; J3.2@53.05,50.222 J3.1@53.05,45.272 53.05,40.59 52.702,40.242 R57.2@52.692,40.242
FAULT_FET1: C31.1 D3.2 J2.6 R35.1 U4.7 | length 39.8
  Top Layer w0.254: D3.2@3.659,11.345 4.961,11.345 5.773,12.157 C31.1@5.773,12.182 5.773,13.381 ; R35.1@5.773,14.58 5.773,13.381 ; v1(6.35,13.278) 6.303,13.325 5.829,13.325 5.773,13.381 ; v1(19,6.599) 19.067,6.599 19.278,6.81 U4.7@20.738,6.81
  Bottom Layer w0.254: J2.6@2.88,26.297 4.034,26.297 4.542,25.789 4.542,24.932 5.183,24.291 5.183,15.621 6.933,13.87 ; v1(6.35,13.278) 6.35,13.287 6.933,13.87 ; v1(19,6.599) 18.977,6.622 14.907,6.622 14.34,7.189 10.638,7.189 10,7.827 10,10.804 6.933,13.87
FAULT_FET2: C32.1 D4.2 J2.8 R36.1 U5.7 | length 45.7
  Top Layer w0.254: v1(2.88,25) 7,29.12 7,35.659 5.675,36.985 R36.1@5.675,37.01 C32.1@5.675,39.205 ; D4.2@3.655,40.066 4.516,39.205 C32.1@5.675,39.205 ; v1(7,39.13) 5.75,39.13 C32.1@5.675,39.205 ; v1(18.481,45.21) 18.51,45.239 20.715,45.239 U5.7@20.738,45.262
  Bottom Layer w0.254: J2.8@2.88,23.757 v1(2.88,25) ; v1(7,39.13) 6.933,39.13 6.785,39.279 6.778,39.279 6.778,47.114 8.494,48.83 12.822,48.83 14.295,47.356 16.335,47.356 v1(18.481,45.21)
G1: J1.5 J1.6 Q3.1 Q3.2 Q3.5 Q3.6 Q3.7 R2.2 R17.2 R20.2 R24.2 R26.2 R27.2 R30.2
  other v1: 49.064,1.368 49.064,2.635 49.064,3.903 49.064,5.17 49.064,6.437 49.064,7.704 49.064,8.971 47.691,9.965 48.572,9.965 47.707,10.801 48.572,10.801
